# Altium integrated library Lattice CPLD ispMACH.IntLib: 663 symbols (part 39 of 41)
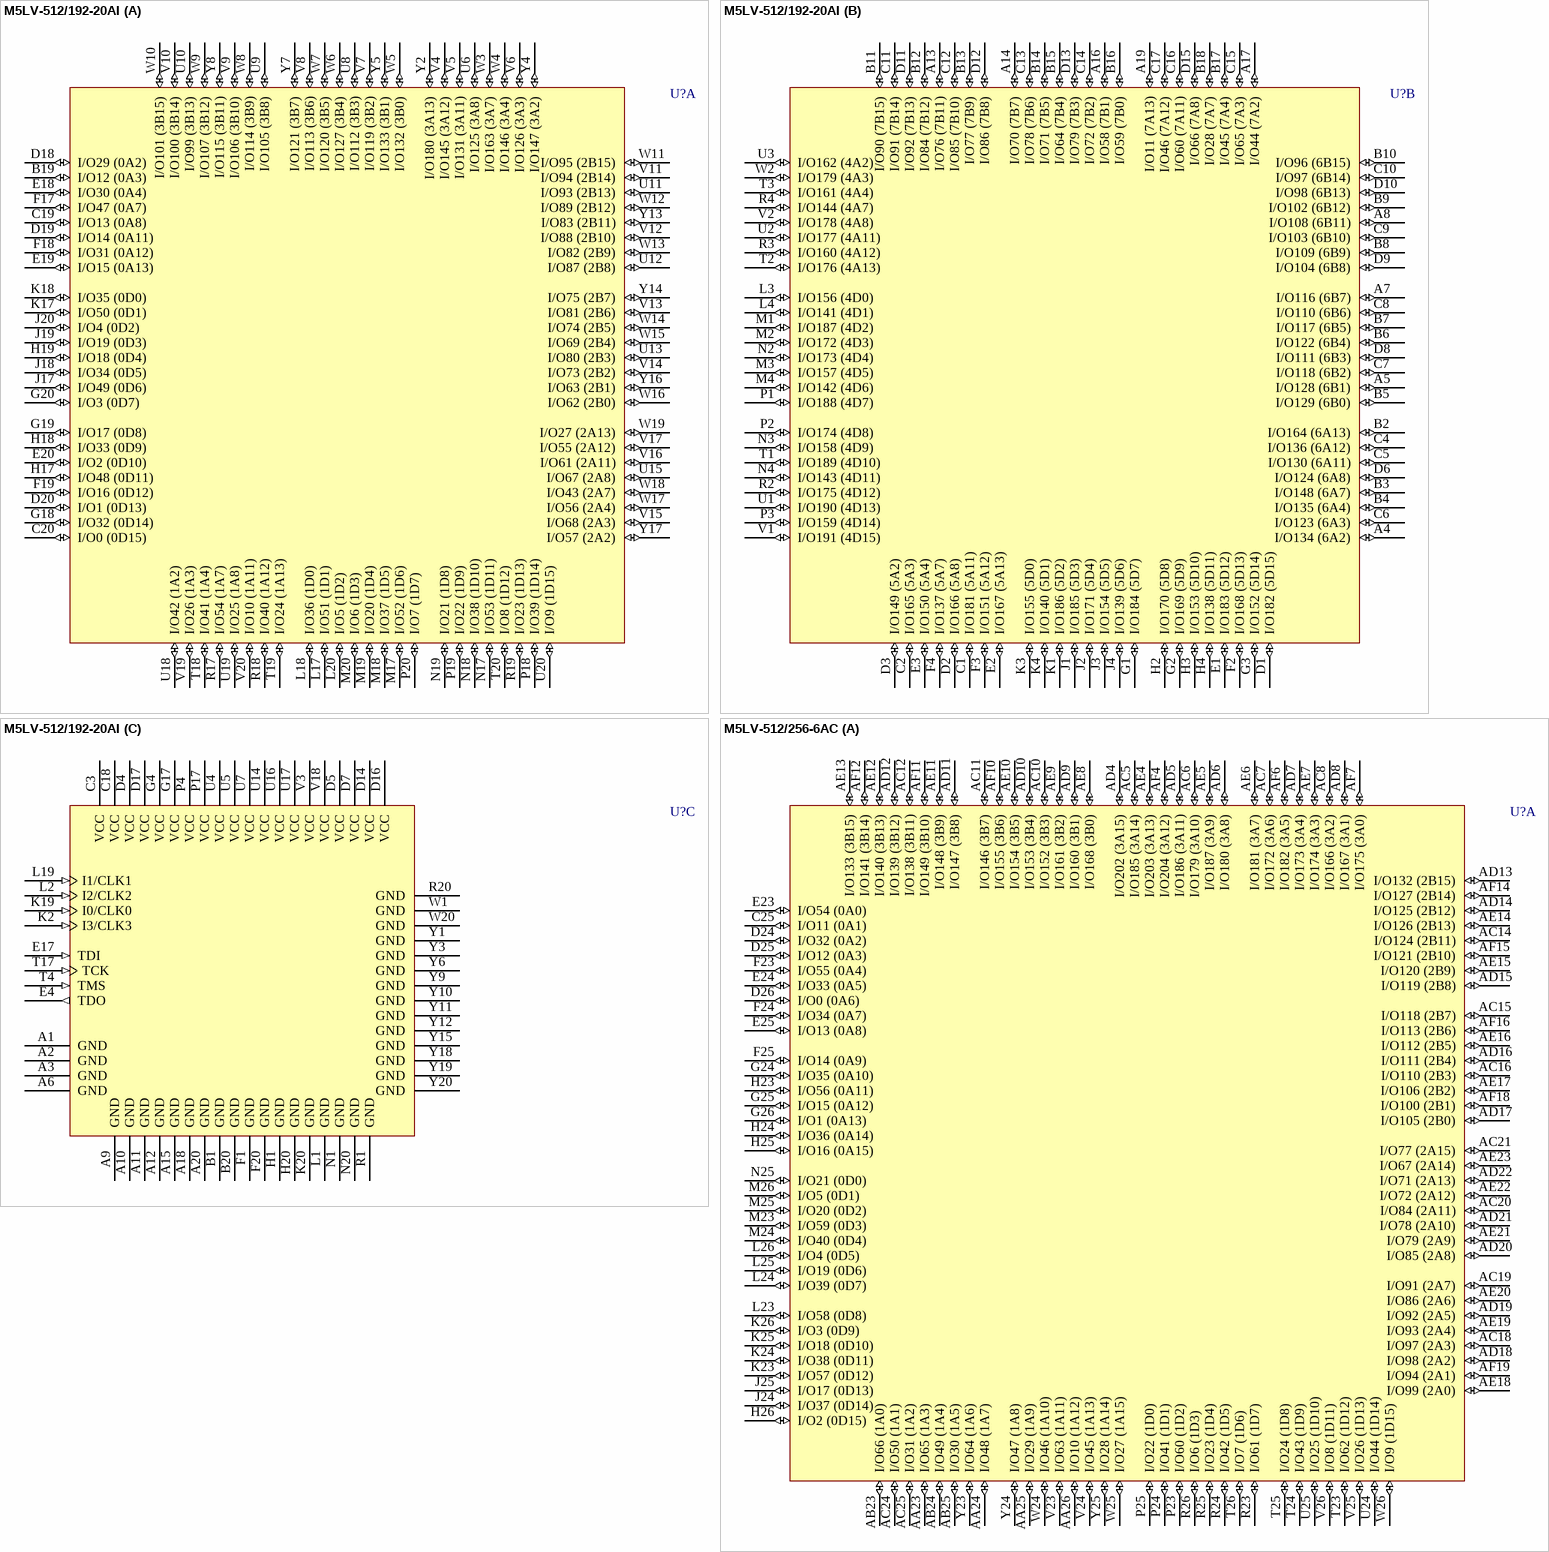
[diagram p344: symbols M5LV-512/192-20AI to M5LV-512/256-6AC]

## M5LV-512/192-20AI
designator U?
High-Density and High-I/O Complex PLD
footprint SBGA256 (BGA, 256-Leads, Body 27x27mm, Pitch 1.27mm)
3D model M5LV-SBGA256 (256-Ball Super Ball Grid Array (SBGA256))
part A pins: B19 I/O12 (0A3) (io), C19 I/O13 (0A8) (io), C20 I/O0 (0D15) (io), D18 I/O29 (0A2) (io), D19 I/O14 (0A11) (io), D20 I/O1 (0D13) (io), E18 I/O30 (0A4) (io), E19 I/O15 (0A13) (io), E20 I/O2 (0D10) (io), F17 I/O47 (0A7) (io), F18 I/O31 (0A12) (io), F19 I/O16 (0D12) (io), G18 I/O32 (0D14) (io), G19 I/O17 (0D8) (io), G20 I/O3 (0D7) (io), H17 I/O48 (0D11) (io), H18 I/O33 (0D9) (io), H19 I/O18 (0D4) (io), J17 I/O49 (0D6) (io), J18 I/O34 (0D5) (io), J19 I/O19 (0D3) (io), J20 I/O4 (0D2) (io), K17 I/O50 (0D1) (io), K18 I/O35 (0D0) (io), L17 I/O51 (1D1) (io), L18 I/O36 (1D0) (io), L20 I/O5 (1D2) (io), M17 I/O52 (1D6) (io), M18 I/O37 (1D5) (io), M19 I/O20 (1D4) (io), M20 I/O6 (1D3) (io), N17 I/O53 (1D11) (io), N18 I/O38 (1D10) (io), N19 I/O21 (1D8) (io), P18 I/O39 (1D14) (io), P19 I/O22 (1D9) (io), P20 I/O7 (1D7) (io), R17 I/O54 (1A7) (io), R18 I/O40 (1A12) (io), R19 I/O23 (1D13) (io), T18 I/O41 (1A4) (io), T19 I/O24 (1A13) (io), T20 I/O8 (1D12) (io), U6 I/O125 (3A8) (io), U8 I/O112 (3B3) (io), U9 I/O105 (3B8) (io), U10 I/O99 (3B13) (io), U11 I/O93 (2B13) (io), U12 I/O87 (2B8) (io), U13 I/O80 (2B3) (io), U15 I/O67 (2A8) (io), U18 I/O42 (1A2) (io), U19 I/O25 (1A8) (io), U20 I/O9 (1D15) (io), V4 I/O145 (3A12) (io), V5 I/O131 (3A11) (io), V6 I/O126 (3A3) (io), V7 I/O119 (3B2) (io), V8 I/O113 (3B6) (io), V9 I/O106 (3B10) (io), V10 I/O100 (3B14) (io), V11 I/O94 (2B14) (io), V12 I/O88 (2B10) (io), V13 I/O81 (2B6) (io), V14 I/O73 (2B2) (io), V15 I/O68 (2A3) (io), V16 I/O61 (2A11) (io), V17 I/O55 (2A12) (io), V19 I/O26 (1A3) (io), V20 I/O10 (1A11) (io), W3 I/O163 (3A7) (io), W4 I/O146 (3A4) (io), W5 I/O132 (3B0) (io), W6 I/O127 (3B4) (io), W7 I/O120 (3B5) (io), W8 I/O114 (3B9) (io), W9 I/O107 (3B12) (io), W10 I/O101 (3B15) (io), W11 I/O95 (2B15) (io), W12 I/O89 (2B12) (io), W13 I/O82 (2B9) (io), W14 I/O74 (2B5) (io), W15 I/O69 (2B4) (io), W16 I/O62 (2B0) (io), W17 I/O56 (2A4) (io), W18 I/O43 (2A7) (io), W19 I/O27 (2A13) (io), Y2 I/O180 (3A13) (io), Y4 I/O147 (3A2) (io), Y5 I/O133 (3B1) (io), Y7 I/O121 (3B7) (io), Y8 I/O115 (3B11) (io), Y13 I/O83 (2B11) (io), Y14 I/O75 (2B7) (io), Y16 I/O63 (2B1) (io), Y17 I/O57 (2A2) (io)
part B pins: A4 I/O134 (6A2) (io), A5 I/O128 (6B1) (io), A7 I/O116 (6B7) (io), A8 I/O108 (6B11) (io), A13 I/O76 (7B11) (io), A14 I/O70 (7B7) (io), A16 I/O58 (7B1) (io), A17 I/O44 (7A2) (io), A19 I/O11 (7A13) (io), B2 I/O164 (6A13) (io), B3 I/O148 (6A7) (io), B4 I/O135 (6A4) (io), B5 I/O129 (6B0) (io), B6 I/O122 (6B4) (io), B7 I/O117 (6B5) (io), B8 I/O109 (6B9) (io), B9 I/O102 (6B12) (io), B10 I/O96 (6B15) (io), B11 I/O90 (7B15) (io), B12 I/O84 (7B12) (io), B13 I/O77 (7B9) (io), B14 I/O71 (7B5) (io), B15 I/O64 (7B4) (io), B16 I/O59 (7B0) (io), B17 I/O45 (7A4) (io), B18 I/O28 (7A7) (io), C1 I/O181 (5A11) (io), C2 I/O165 (5A3) (io), C4 I/O136 (6A12) (io), C5 I/O130 (6A11) (io), C6 I/O123 (6A3) (io), C7 I/O118 (6B2) (io), C8 I/O110 (6B6) (io), C9 I/O103 (6B10) (io), C10 I/O97 (6B14) (io), C11 I/O91 (7B14) (io), C12 I/O85 (7B10) (io), C13 I/O78 (7B6) (io), C14 I/O72 (7B2) (io), C15 I/O65 (7A3) (io), C16 I/O60 (7A11) (io), C17 I/O46 (7A12) (io), D1 I/O182 (5D15) (io), D2 I/O166 (5A8) (io), D3 I/O149 (5A2) (io), D6 I/O124 (6A8) (io), D8 I/O111 (6B3) (io), D9 I/O104 (6B8) (io), D10 I/O98 (6B13) (io), D11 I/O92 (7B13) (io), D12 I/O86 (7B8) (io), D13 I/O79 (7B3) (io), D15 I/O66 (7A8) (io), E1 I/O183 (5D12) (io), E2 I/O167 (5A13) (io), E3 I/O150 (5A4) (io), F2 I/O168 (5D13) (io), F3 I/O151 (5A12) (io), F4 I/O137 (5A7) (io), G1 I/O184 (5D7) (io), G2 I/O169 (5D9) (io), G3 I/O152 (5D14) (io), H2 I/O170 (5D8) (io), H3 I/O153 (5D10) (io), H4 I/O138 (5D11) (io), J1 I/O185 (5D3) (io), J2 I/O171 (5D4) (io), J3 I/O154 (5D5) (io), J4 I/O139 (5D6) (io), K1 I/O186 (5D2) (io), K3 I/O155 (5D0) (io), K4 I/O140 (5D1) (io), L3 I/O156 (4D0) (io), L4 I/O141 (4D1) (io), M1 I/O187 (4D2) (io), M2 I/O172 (4D3) (io), M3 I/O157 (4D5) (io), M4 I/O142 (4D6) (io), N2 I/O173 (4D4) (io), N3 I/O158 (4D9) (io), N4 I/O143 (4D11) (io), P1 I/O188 (4D7) (io), P2 I/O174 (4D8) (io), P3 I/O159 (4D14) (io), R2 I/O175 (4D12) (io), R3 I/O160 (4A12) (io), R4 I/O144 (4A7) (io), T1 I/O189 (4D10) (io), T2 I/O176 (4A13) (io), T3 I/O161 (4A4) (io), U1 I/O190 (4D13) (io), U2 I/O177 (4A11) (io), U3 I/O162 (4A2) (io), V1 I/O191 (4D15) (io), V2 I/O178 (4A8) (io), W2 I/O179 (4A3) (io)
part C pins: A1 GND (power), A2 GND (power), A3 GND (power), A6 GND (power), A9 GND (power), A10 GND (power), A11 GND (power), A12 GND (power), A15 GND (power), A18 GND (power), A20 GND (power), B1 GND (power), B20 GND (power), C3 VCC (power), C18 VCC (power), D4 VCC (power), D5 VCC (power), D7 VCC (power), D14 VCC (power), D16 VCC (power), D17 VCC (power), E4 TDO (out), E17 TDI (in), F1 GND (power), F20 GND (power), G4 VCC (power), G17 VCC (power), H1 GND (power), H20 GND (power), K2 I3/CLK3 (in), K19 I0/CLK0 (in), K20 GND (power), L1 GND (power), L2 I2/CLK2 (in), L19 I1/CLK1 (in), N1 GND (power), N20 GND (power), P4 VCC (power), P17 VCC (power), R1 GND (power), R20 GND (power), T4 TMS (in), T17 TCK (in), U4 VCC (power), U5 VCC (power), U7 VCC (power), U14 VCC (power), U16 VCC (power), U17 VCC (power), V3 VCC (power), V18 VCC (power), W1 GND (power), W20 GND (power), Y1 GND (power), Y3 GND (power), Y6 GND (power), Y9 GND (power), Y10 GND (power), Y11 GND (power), Y12 GND (power), Y15 GND (power), Y18 GND (power), Y19 GND (power), Y20 GND (power)

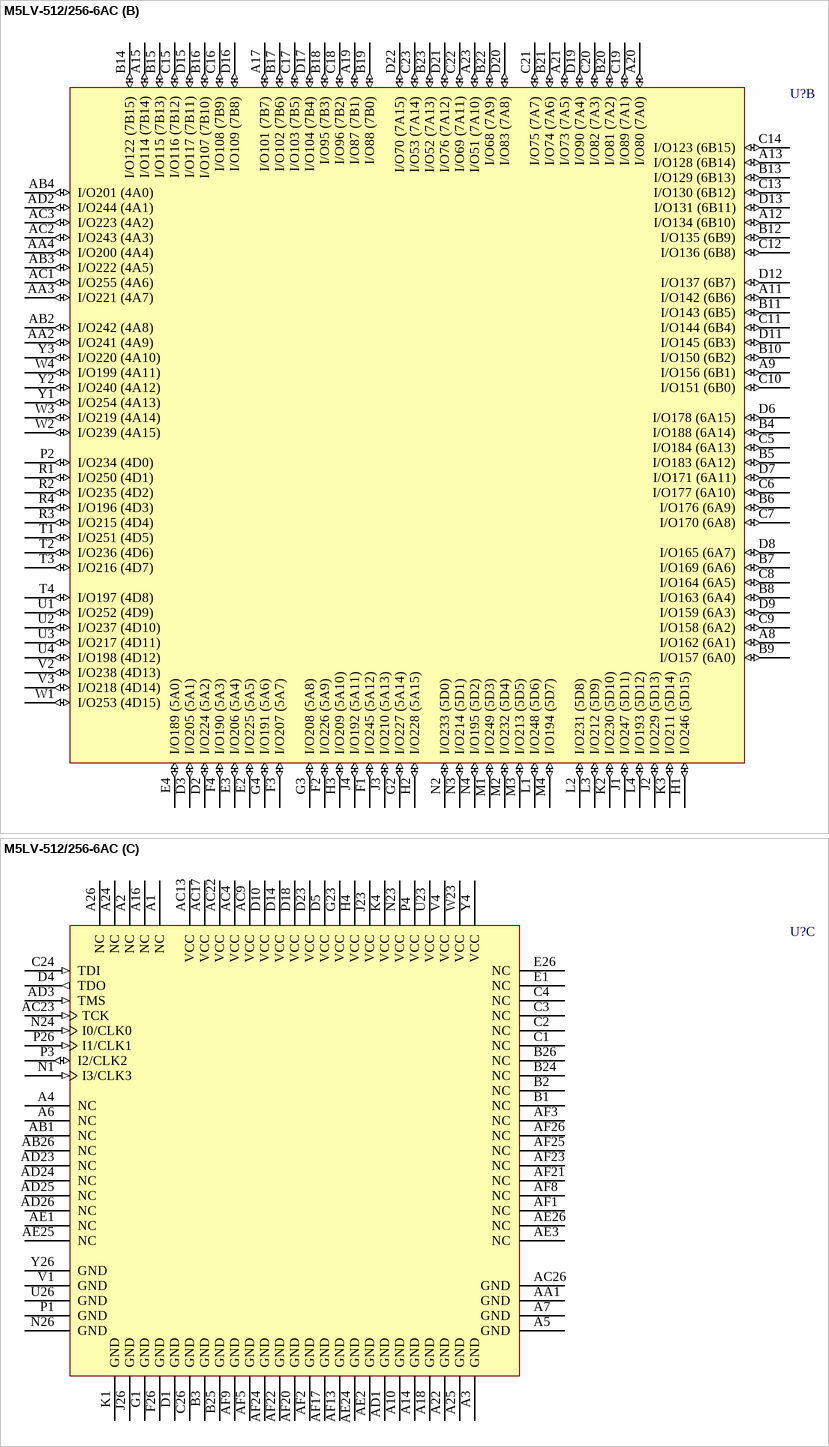
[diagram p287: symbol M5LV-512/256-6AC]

## M5LV-512/256-6AC
designator U?
High-Density and High-I/O Complex PLD
footprint SBGA352 (BGA, 352-Leads, Body 35x35mm, Pitch 1.27mm)
3D model M5LV-SBGA352 (352-Ball Super Ball Grid Array (SBGA352))
part A pins: AA23 I/O65 (1A3) (io), AA24 I/O48 (1A7) (io), AA25 I/O29 (1A9) (io), AA26 I/O10 (1A12) (io), AB23 I/O66 (1A0) (io), AB24 I/O49 (1A4) (io), AB25 I/O30 (1A5) (io), AC5 I/O185 (3A14) (io), AC6 I/O179 (3A10) (io), AC7 I/O172 (3A6) (io), AC8 I/O166 (3A2) (io), AC10 I/O152 (3B3) (io), AC11 I/O146 (3B7) (io), AC12 I/O138 (3B11) (io), AC14 I/O124 (2B11) (io), AC15 I/O118 (2B7) (io), AC16 I/O110 (2B3) (io), AC18 I/O97 (2A3) (io), AC19 I/O91 (2A7) (io), AC20 I/O84 (2A11) (io), AC21 I/O77 (2A15) (io), AC24 I/O50 (1A1) (io), AC25 I/O31 (1A2) (io), AD4 I/O202 (3A15) (io), AD5 I/O186 (3A11) (io), AD6 I/O180 (3A8) (io), AD7 I/O173 (3A4) (io), AD8 I/O167 (3A1) (io), AD9 I/O160 (3B1) (io), AD10 I/O153 (3B4) (io), AD11 I/O147 (3B8) (io), AD12 I/O139 (3B12) (io), AD13 I/O132 (2B15) (io), AD14 I/O125 (2B12) (io), AD15 I/O119 (2B8) (io), AD16 I/O111 (2B4) (io), AD17 I/O105 (2B0) (io), AD18 I/O98 (2A2) (io), AD19 I/O92 (2A5) (io), AD20 I/O85 (2A8) (io), AD21 I/O78 (2A10) (io), AD22 I/O71 (2A13) (io), AE4 I/O203 (3A13) (io), AE5 I/O187 (3A9) (io), AE6 I/O181 (3A7) (io), AE7 I/O174 (3A3) (io), AE8 I/O168 (3B0) (io), AE9 I/O161 (3B2) (io), AE10 I/O154 (3B5) (io), AE11 I/O148 (3B9) (io), AE12 I/O140 (3B13) (io), AE13 I/O133 (3B15) (io), AE14 I/O126 (2B13) (io), AE15 I/O120 (2B9) (io), AE16 I/O112 (2B5) (io), AE17 I/O106 (2B2) (io), AE18 I/O99 (2A0) (io), AE19 I/O93 (2A4) (io), AE20 I/O86 (2A6) (io), AE21 I/O79 (2A9) (io), AE22 I/O72 (2A12) (io), AE23 I/O67 (2A14) (io), AF4 I/O204 (3A12) (io), AF6 I/O182 (3A5) (io), AF7 I/O175 (3A0) (io), AF10 I/O155 (3B6) (io), AF11 I/O149 (3B10) (io), AF12 I/O141 (3B14) (io), AF14 I/O127 (2B14) (io), AF15 I/O121 (2B10) (io), AF16 I/O113 (2B6) (io), AF18 I/O100 (2B1) (io), AF19 I/O94 (2A1) (io), C25 I/O11 (0A1) (io), D24 I/O32 (0A2) (io), D25 I/O12 (0A3) (io), D26 I/O0 (0A6) (io), E23 I/O54 (0A0) (io), E24 I/O33 (0A5) (io), E25 I/O13 (0A8) (io), F23 I/O55 (0A4) (io), F24 I/O34 (0A7) (io), F25 I/O14 (0A9) (io), G24 I/O35 (0A10) (io), G25 I/O15 (0A12) (io), G26 I/O1 (0A13) (io), H23 I/O56 (0A11) (io), H24 I/O36 (0A14) (io), H25 I/O16 (0A15) (io), H26 I/O2 (0D15) (io), J24 I/O37 (0D14) (io), J25 I/O17 (0D13) (io), K23 I/O57 (0D12) (io), K24 I/O38 (0D11) (io), K25 I/O18 (0D10) (io), K26 I/O3 (0D9) (io), L23 I/O58 (0D8) (io), L24 I/O39 (0D7) (io), L25 I/O19 (0D6) (io), L26 I/O4 (0D5) (io), M23 I/O59 (0D3) (io), M24 I/O40 (0D4) (io), M25 I/O20 (0D2) (io), M26 I/O5 (0D1) (io), N25 I/O21 (0D0) (io), P23 I/O60 (1D2) (io), P24 I/O41 (1D1) (io), P25 I/O22 (1D0) (io), R23 I/O61 (1D7) (io), R24 I/O42 (1D5) (io), R25 I/O23 (1D4) (io), R26 I/O6 (1D3) (io), T23 I/O62 (1D12) (io), T24 I/O43 (1D9) (io), T25 I/O24 (1D8) (io), T26 I/O7 (1D6) (io), U24 I/O44 (1D14) (io), U25 I/O25 (1D10) (io), V23 I/O63 (1A11) (io), V24 I/O45 (1A13) (io), V25 I/O26 (1D13) (io), V26 I/O8 (1D11) (io), W24 I/O46 (1A10) (io), W25 I/O27 (1A15) (io), W26 I/O9 (1D15) (io), Y23 I/O64 (1A6) (io), Y24 I/O47 (1A8) (io), Y25 I/O28 (1A14) (io)
part B pins: A8 I/O162 (6A1) (io), A9 I/O156 (6B1) (io), A11 I/O142 (6B6) (io), A12 I/O134 (6B10) (io), A13 I/O128 (6B14) (io), A15 I/O114 (7B14) (io), A17 I/O101 (7B7) (io), A19 I/O87 (7B1) (io), A20 I/O80 (7A0) (io), A21 I/O73 (7A5) (io), A23 I/O51 (7A10) (io), AA2 I/O241 (4A9) (io), AA3 I/O221 (4A7) (io), AA4 I/O200 (4A4) (io), AB2 I/O242 (4A8) (io), AB3 I/O222 (4A5) (io), AB4 I/O201 (4A0) (io), AC1 I/O255 (4A6) (io), AC2 I/O243 (4A3) (io), AC3 I/O223 (4A2) (io), AD2 I/O244 (4A1) (io), B4 I/O188 (6A14) (io), B5 I/O183 (6A12) (io), B6 I/O176 (6A9) (io), B7 I/O169 (6A6) (io), B8 I/O163 (6A4) (io), B9 I/O157 (6A0) (io), B10 I/O150 (6B2) (io), B11 I/O143 (6B5) (io), B12 I/O135 (6B9) (io), B13 I/O129 (6B13) (io), B14 I/O122 (7B15) (io), B15 I/O115 (7B13) (io), B16 I/O107 (7B10) (io), B17 I/O102 (7B6) (io), B18 I/O95 (7B3) (io), B19 I/O88 (7B0) (io), B20 I/O81 (7A2) (io), B21 I/O74 (7A6) (io), B22 I/O68 (7A9) (io), B23 I/O52 (7A13) (io), C5 I/O184 (6A13) (io), C6 I/O177 (6A10) (io), C7 I/O170 (6A8) (io), C8 I/O164 (6A5) (io), C9 I/O158 (6A2) (io), C10 I/O151 (6B0) (io), C11 I/O144 (6B4) (io), C12 I/O136 (6B8) (io), C13 I/O130 (6B12) (io), C14 I/O123 (6B15) (io), C15 I/O116 (7B12) (io), C16 I/O108 (7B9) (io), C17 I/O103 (7B5) (io), C18 I/O96 (7B2) (io), C19 I/O89 (7A1) (io), C20 I/O82 (7A3) (io), C21 I/O75 (7A7) (io), C22 I/O69 (7A11) (io), C23 I/O53 (7A14) (io), D2 I/O224 (5A2) (io), D3 I/O205 (5A1) (io), D6 I/O178 (6A15) (io), D7 I/O171 (6A11) (io), D8 I/O165 (6A7) (io), D9 I/O159 (6A3) (io), D11 I/O145 (6B3) (io), D12 I/O137 (6B7) (io), D13 I/O131 (6B11) (io), D15 I/O117 (7B11) (io), D16 I/O109 (7B8) (io), D17 I/O104 (7B4) (io), D19 I/O90 (7A4) (io), D20 I/O83 (7A8) (io), D21 I/O76 (7A12) (io), D22 I/O70 (7A15) (io), E2 I/O225 (5A5) (io), E3 I/O206 (5A4) (io), E4 I/O189 (5A0) (io), F1 I/O245 (5A12) (io), F2 I/O226 (5A9) (io), F3 I/O207 (5A7) (io), F4 I/O190 (5A3) (io), G2 I/O227 (5A14) (io), G3 I/O208 (5A8) (io), G4 I/O191 (5A6) (io), H1 I/O246 (5D15) (io), H2 I/O228 (5A15) (io), H3 I/O209 (5A10) (io), J1 I/O247 (5D11) (io), J2 I/O229 (5D13) (io), J3 I/O210 (5A13) (io), J4 I/O192 (5A11) (io), K2 I/O230 (5D10) (io), K3 I/O211 (5D14) (io), L1 I/O248 (5D6) (io), L2 I/O231 (5D8) (io), L3 I/O212 (5D9) (io), L4 I/O193 (5D12) (io), M1 I/O249 (5D3) (io), M2 I/O232 (5D4) (io), M3 I/O213 (5D5) (io), M4 I/O194 (5D7) (io), N2 I/O233 (5D0) (io), N3 I/O214 (5D1) (io), N4 I/O195 (5D2) (io), P2 I/O234 (4D0) (io), R1 I/O250 (4D1) (io), R2 I/O235 (4D2) (io), R3 I/O215 (4D4) (io), R4 I/O196 (4D3) (io), T1 I/O251 (4D5) (io), T2 I/O236 (4D6) (io), T3 I/O216 (4D7) (io), T4 I/O197 (4D8) (io), U1 I/O252 (4D9) (io), U2 I/O237 (4D10) (io), U3 I/O217 (4D11) (io), U4 I/O198 (4D12) (io), V2 I/O238 (4D13) (io), V3 I/O218 (4D14) (io), W1 I/O253 (4D15) (io), W2 I/O239 (4A15) (io), W3 I/O219 (4A14) (io), W4 I/O199 (4A11) (io), Y1 I/O254 (4A13) (io), Y2 I/O240 (4A12) (io), Y3 I/O220 (4A10) (io)
part C pins: A1 NC, A2 NC, A3 GND (power), A4 NC, A5 GND (power), A6 NC, A7 GND (power), A10 GND (power), A14 GND (power), A16 NC, A18 GND (power), A22 GND (power), A24 NC, A25 GND (power), A26 NC, AA1 GND (power), AB1 NC, AB26 NC, AC4 VCC (power), AC9 VCC (power), AC13 VCC (power), AC17 VCC (power), AC22 VCC (power), AC23 TCK (in), AC26 GND (power), AD1 GND (power), AD3 TMS (in), AD23 NC, AD24 NC, AD25 NC, AD26 NC, AE1 NC, AE2 GND (power), AE3 NC, AE24 GND (power), AE25 NC, AE26 NC, AF1 NC, AF2 GND (power), AF3 NC, AF5 GND (power), AF8 NC, AF9 GND (power), AF13 GND (power), AF17 GND (power), AF20 GND (power), AF21 NC, AF22 GND (power), AF23 NC, AF24 GND (power), AF25 NC, AF26 NC, B1 NC, B2 NC, B3 GND (power), B24 NC, B25 GND (power), B26 NC, C1 NC, C2 NC, C3 NC, C4 NC, C24 TDI (in), C26 GND (power), D1 GND (power), D4 TDO (out), D5 VCC (power), D10 VCC (power), D14 VCC (power), D18 VCC (power), D23 VCC (power), E1 NC, E26 NC, F26 GND (power), G1 GND (power), G23 VCC (power), H4 VCC (power), J23 VCC (power), J26 GND (power), K1 GND (power), K4 VCC (power), N1 I3/CLK3 (in), N23 VCC (power), N24 I0/CLK0 (in), N26 GND (power), P1 GND (power), P3 I2/CLK2 (io), P4 VCC (power), P26 I1/CLK1 (in), U23 VCC (power), U26 GND (power), V1 GND (power), V4 VCC (power), W23 VCC (power), Y4 VCC (power), Y26 GND (power)

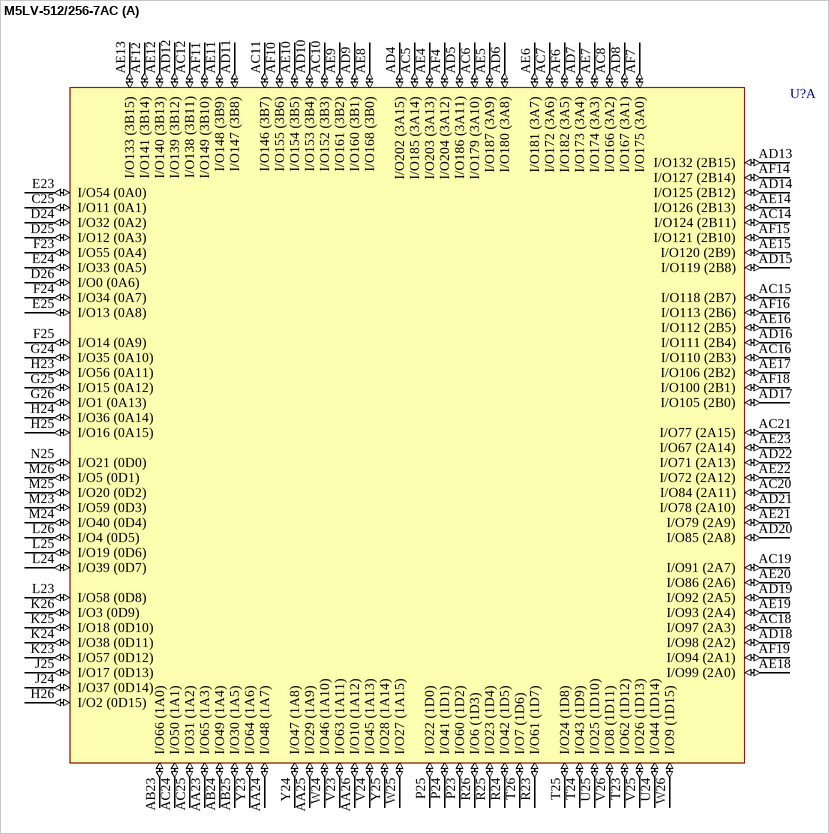
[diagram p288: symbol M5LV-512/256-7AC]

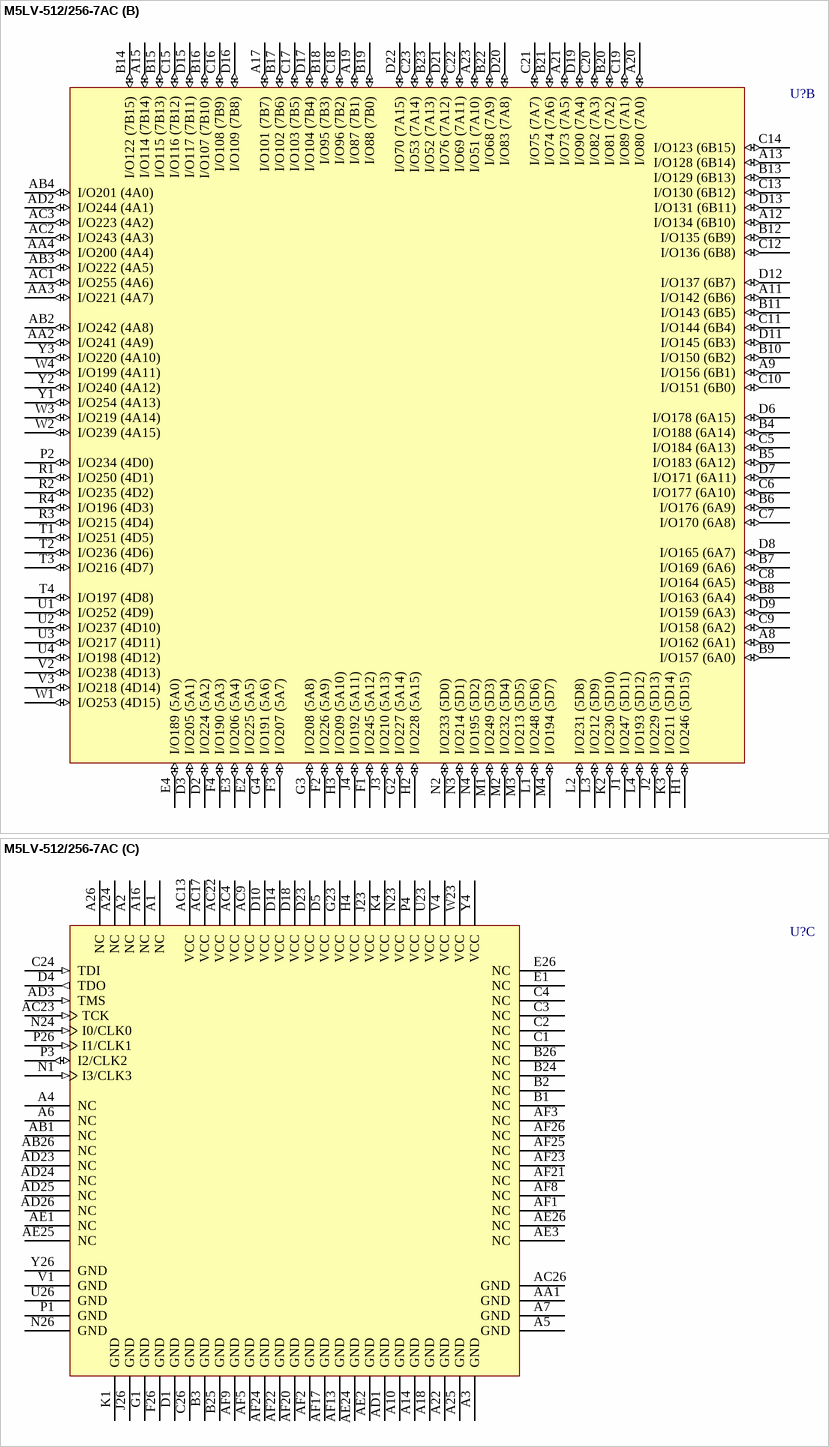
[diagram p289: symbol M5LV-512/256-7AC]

## M5LV-512/256-7AC
designator U?
High-Density and High-I/O Complex PLD
footprint SBGA352 (BGA, 352-Leads, Body 35x35mm, Pitch 1.27mm)
3D model M5LV-SBGA352 (352-Ball Super Ball Grid Array (SBGA352))
part A pins: AA23 I/O65 (1A3) (io), AA24 I/O48 (1A7) (io), AA25 I/O29 (1A9) (io), AA26 I/O10 (1A12) (io), AB23 I/O66 (1A0) (io), AB24 I/O49 (1A4) (io), AB25 I/O30 (1A5) (io), AC5 I/O185 (3A14) (io), AC6 I/O179 (3A10) (io), AC7 I/O172 (3A6) (io), AC8 I/O166 (3A2) (io), AC10 I/O152 (3B3) (io), AC11 I/O146 (3B7) (io), AC12 I/O138 (3B11) (io), AC14 I/O124 (2B11) (io), AC15 I/O118 (2B7) (io), AC16 I/O110 (2B3) (io), AC18 I/O97 (2A3) (io), AC19 I/O91 (2A7) (io), AC20 I/O84 (2A11) (io), AC21 I/O77 (2A15) (io), AC24 I/O50 (1A1) (io), AC25 I/O31 (1A2) (io), AD4 I/O202 (3A15) (io), AD5 I/O186 (3A11) (io), AD6 I/O180 (3A8) (io), AD7 I/O173 (3A4) (io), AD8 I/O167 (3A1) (io), AD9 I/O160 (3B1) (io), AD10 I/O153 (3B4) (io), AD11 I/O147 (3B8) (io), AD12 I/O139 (3B12) (io), AD13 I/O132 (2B15) (io), AD14 I/O125 (2B12) (io), AD15 I/O119 (2B8) (io), AD16 I/O111 (2B4) (io), AD17 I/O105 (2B0) (io), AD18 I/O98 (2A2) (io), AD19 I/O92 (2A5) (io), AD20 I/O85 (2A8) (io), AD21 I/O78 (2A10) (io), AD22 I/O71 (2A13) (io), AE4 I/O203 (3A13) (io), AE5 I/O187 (3A9) (io), AE6 I/O181 (3A7) (io), AE7 I/O174 (3A3) (io), AE8 I/O168 (3B0) (io), AE9 I/O161 (3B2) (io), AE10 I/O154 (3B5) (io), AE11 I/O148 (3B9) (io), AE12 I/O140 (3B13) (io), AE13 I/O133 (3B15) (io), AE14 I/O126 (2B13) (io), AE15 I/O120 (2B9) (io), AE16 I/O112 (2B5) (io), AE17 I/O106 (2B2) (io), AE18 I/O99 (2A0) (io), AE19 I/O93 (2A4) (io), AE20 I/O86 (2A6) (io), AE21 I/O79 (2A9) (io), AE22 I/O72 (2A12) (io), AE23 I/O67 (2A14) (io), AF4 I/O204 (3A12) (io), AF6 I/O182 (3A5) (io), AF7 I/O175 (3A0) (io), AF10 I/O155 (3B6) (io), AF11 I/O149 (3B10) (io), AF12 I/O141 (3B14) (io), AF14 I/O127 (2B14) (io), AF15 I/O121 (2B10) (io), AF16 I/O113 (2B6) (io), AF18 I/O100 (2B1) (io), AF19 I/O94 (2A1) (io), C25 I/O11 (0A1) (io), D24 I/O32 (0A2) (io), D25 I/O12 (0A3) (io), D26 I/O0 (0A6) (io), E23 I/O54 (0A0) (io), E24 I/O33 (0A5) (io), E25 I/O13 (0A8) (io), F23 I/O55 (0A4) (io), F24 I/O34 (0A7) (io), F25 I/O14 (0A9) (io), G24 I/O35 (0A10) (io), G25 I/O15 (0A12) (io), G26 I/O1 (0A13) (io), H23 I/O56 (0A11) (io), H24 I/O36 (0A14) (io), H25 I/O16 (0A15) (io), H26 I/O2 (0D15) (io), J24 I/O37 (0D14) (io), J25 I/O17 (0D13) (io), K23 I/O57 (0D12) (io), K24 I/O38 (0D11) (io), K25 I/O18 (0D10) (io), K26 I/O3 (0D9) (io), L23 I/O58 (0D8) (io), L24 I/O39 (0D7) (io), L25 I/O19 (0D6) (io), L26 I/O4 (0D5) (io), M23 I/O59 (0D3) (io), M24 I/O40 (0D4) (io), M25 I/O20 (0D2) (io), M26 I/O5 (0D1) (io), N25 I/O21 (0D0) (io), P23 I/O60 (1D2) (io), P24 I/O41 (1D1) (io), P25 I/O22 (1D0) (io), R23 I/O61 (1D7) (io), R24 I/O42 (1D5) (io), R25 I/O23 (1D4) (io), R26 I/O6 (1D3) (io), T23 I/O62 (1D12) (io), T24 I/O43 (1D9) (io), T25 I/O24 (1D8) (io), T26 I/O7 (1D6) (io), U24 I/O44 (1D14) (io), U25 I/O25 (1D10) (io), V23 I/O63 (1A11) (io), V24 I/O45 (1A13) (io), V25 I/O26 (1D13) (io), V26 I/O8 (1D11) (io), W24 I/O46 (1A10) (io), W25 I/O27 (1A15) (io), W26 I/O9 (1D15) (io), Y23 I/O64 (1A6) (io), Y24 I/O47 (1A8) (io), Y25 I/O28 (1A14) (io)
part B pins: A8 I/O162 (6A1) (io), A9 I/O156 (6B1) (io), A11 I/O142 (6B6) (io), A12 I/O134 (6B10) (io), A13 I/O128 (6B14) (io), A15 I/O114 (7B14) (io), A17 I/O101 (7B7) (io), A19 I/O87 (7B1) (io), A20 I/O80 (7A0) (io), A21 I/O73 (7A5) (io), A23 I/O51 (7A10) (io), AA2 I/O241 (4A9) (io), AA3 I/O221 (4A7) (io), AA4 I/O200 (4A4) (io), AB2 I/O242 (4A8) (io), AB3 I/O222 (4A5) (io), AB4 I/O201 (4A0) (io), AC1 I/O255 (4A6) (io), AC2 I/O243 (4A3) (io), AC3 I/O223 (4A2) (io), AD2 I/O244 (4A1) (io), B4 I/O188 (6A14) (io), B5 I/O183 (6A12) (io), B6 I/O176 (6A9) (io), B7 I/O169 (6A6) (io), B8 I/O163 (6A4) (io), B9 I/O157 (6A0) (io), B10 I/O150 (6B2) (io), B11 I/O143 (6B5) (io), B12 I/O135 (6B9) (io), B13 I/O129 (6B13) (io), B14 I/O122 (7B15) (io), B15 I/O115 (7B13) (io), B16 I/O107 (7B10) (io), B17 I/O102 (7B6) (io), B18 I/O95 (7B3) (io), B19 I/O88 (7B0) (io), B20 I/O81 (7A2) (io), B21 I/O74 (7A6) (io), B22 I/O68 (7A9) (io), B23 I/O52 (7A13) (io), C5 I/O184 (6A13) (io), C6 I/O177 (6A10) (io), C7 I/O170 (6A8) (io), C8 I/O164 (6A5) (io), C9 I/O158 (6A2) (io), C10 I/O151 (6B0) (io), C11 I/O144 (6B4) (io), C12 I/O136 (6B8) (io), C13 I/O130 (6B12) (io), C14 I/O123 (6B15) (io), C15 I/O116 (7B12) (io), C16 I/O108 (7B9) (io), C17 I/O103 (7B5) (io), C18 I/O96 (7B2) (io), C19 I/O89 (7A1) (io), C20 I/O82 (7A3) (io), C21 I/O75 (7A7) (io), C22 I/O69 (7A11) (io), C23 I/O53 (7A14) (io), D2 I/O224 (5A2) (io), D3 I/O205 (5A1) (io), D6 I/O178 (6A15) (io), D7 I/O171 (6A11) (io), D8 I/O165 (6A7) (io), D9 I/O159 (6A3) (io), D11 I/O145 (6B3) (io), D12 I/O137 (6B7) (io), D13 I/O131 (6B11) (io), D15 I/O117 (7B11) (io), D16 I/O109 (7B8) (io), D17 I/O104 (7B4) (io), D19 I/O90 (7A4) (io), D20 I/O83 (7A8) (io), D21 I/O76 (7A12) (io), D22 I/O70 (7A15) (io), E2 I/O225 (5A5) (io), E3 I/O206 (5A4) (io), E4 I/O189 (5A0) (io), F1 I/O245 (5A12) (io), F2 I/O226 (5A9) (io), F3 I/O207 (5A7) (io), F4 I/O190 (5A3) (io), G2 I/O227 (5A14) (io), G3 I/O208 (5A8) (io), G4 I/O191 (5A6) (io), H1 I/O246 (5D15) (io), H2 I/O228 (5A15) (io), H3 I/O209 (5A10) (io), J1 I/O247 (5D11) (io), J2 I/O229 (5D13) (io), J3 I/O210 (5A13) (io), J4 I/O192 (5A11) (io), K2 I/O230 (5D10) (io), K3 I/O211 (5D14) (io), L1 I/O248 (5D6) (io), L2 I/O231 (5D8) (io), L3 I/O212 (5D9) (io), L4 I/O193 (5D12) (io), M1 I/O249 (5D3) (io), M2 I/O232 (5D4) (io), M3 I/O213 (5D5) (io), M4 I/O194 (5D7) (io), N2 I/O233 (5D0) (io), N3 I/O214 (5D1) (io), N4 I/O195 (5D2) (io), P2 I/O234 (4D0) (io), R1 I/O250 (4D1) (io), R2 I/O235 (4D2) (io), R3 I/O215 (4D4) (io), R4 I/O196 (4D3) (io), T1 I/O251 (4D5) (io), T2 I/O236 (4D6) (io), T3 I/O216 (4D7) (io), T4 I/O197 (4D8) (io), U1 I/O252 (4D9) (io), U2 I/O237 (4D10) (io), U3 I/O217 (4D11) (io), U4 I/O198 (4D12) (io), V2 I/O238 (4D13) (io), V3 I/O218 (4D14) (io), W1 I/O253 (4D15) (io), W2 I/O239 (4A15) (io), W3 I/O219 (4A14) (io), W4 I/O199 (4A11) (io), Y1 I/O254 (4A13) (io), Y2 I/O240 (4A12) (io), Y3 I/O220 (4A10) (io)
part C pins: A1 NC, A2 NC, A3 GND (power), A4 NC, A5 GND (power), A6 NC, A7 GND (power), A10 GND (power), A14 GND (power), A16 NC, A18 GND (power), A22 GND (power), A24 NC, A25 GND (power), A26 NC, AA1 GND (power), AB1 NC, AB26 NC, AC4 VCC (power), AC9 VCC (power), AC13 VCC (power), AC17 VCC (power), AC22 VCC (power), AC23 TCK (in), AC26 GND (power), AD1 GND (power), AD3 TMS (in), AD23 NC, AD24 NC, AD25 NC, AD26 NC, AE1 NC, AE2 GND (power), AE3 NC, AE24 GND (power), AE25 NC, AE26 NC, AF1 NC, AF2 GND (power), AF3 NC, AF5 GND (power), AF8 NC, AF9 GND (power), AF13 GND (power), AF17 GND (power), AF20 GND (power), AF21 NC, AF22 GND (power), AF23 NC, AF24 GND (power), AF25 NC, AF26 NC, B1 NC, B2 NC, B3 GND (power), B24 NC, B25 GND (power), B26 NC, C1 NC, C2 NC, C3 NC, C4 NC, C24 TDI (in), C26 GND (power), D1 GND (power), D4 TDO (out), D5 VCC (power), D10 VCC (power), D14 VCC (power), D18 VCC (power), D23 VCC (power), E1 NC, E26 NC, F26 GND (power), G1 GND (power), G23 VCC (power), H4 VCC (power), J23 VCC (power), J26 GND (power), K1 GND (power), K4 VCC (power), N1 I3/CLK3 (in), N23 VCC (power), N24 I0/CLK0 (in), N26 GND (power), P1 GND (power), P3 I2/CLK2 (io), P4 VCC (power), P26 I1/CLK1 (in), U23 VCC (power), U26 GND (power), V1 GND (power), V4 VCC (power), W23 VCC (power), Y4 VCC (power), Y26 GND (power)

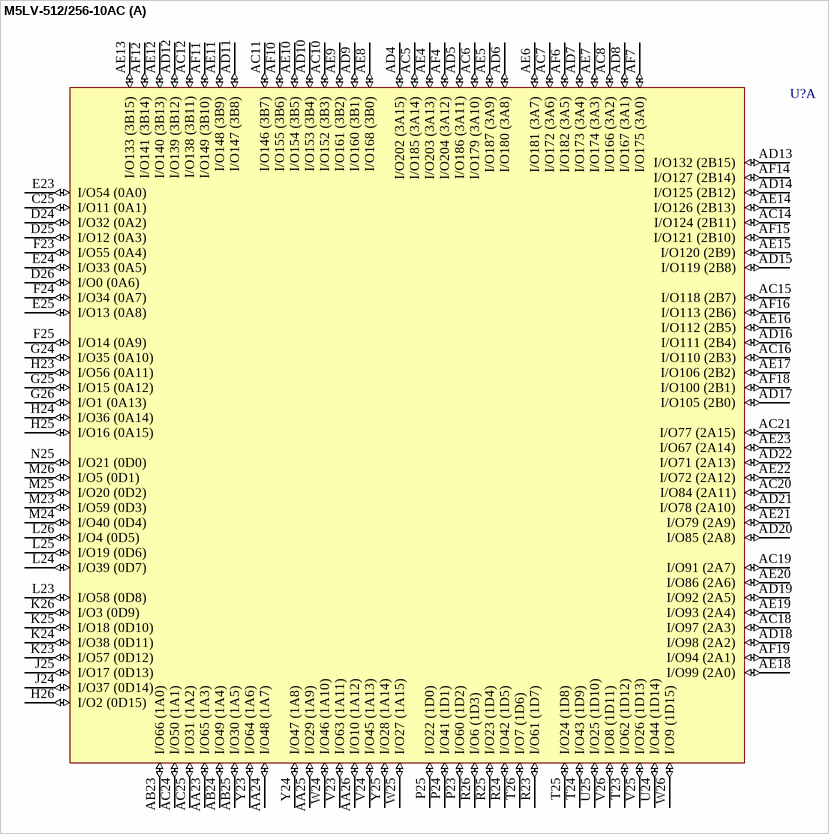
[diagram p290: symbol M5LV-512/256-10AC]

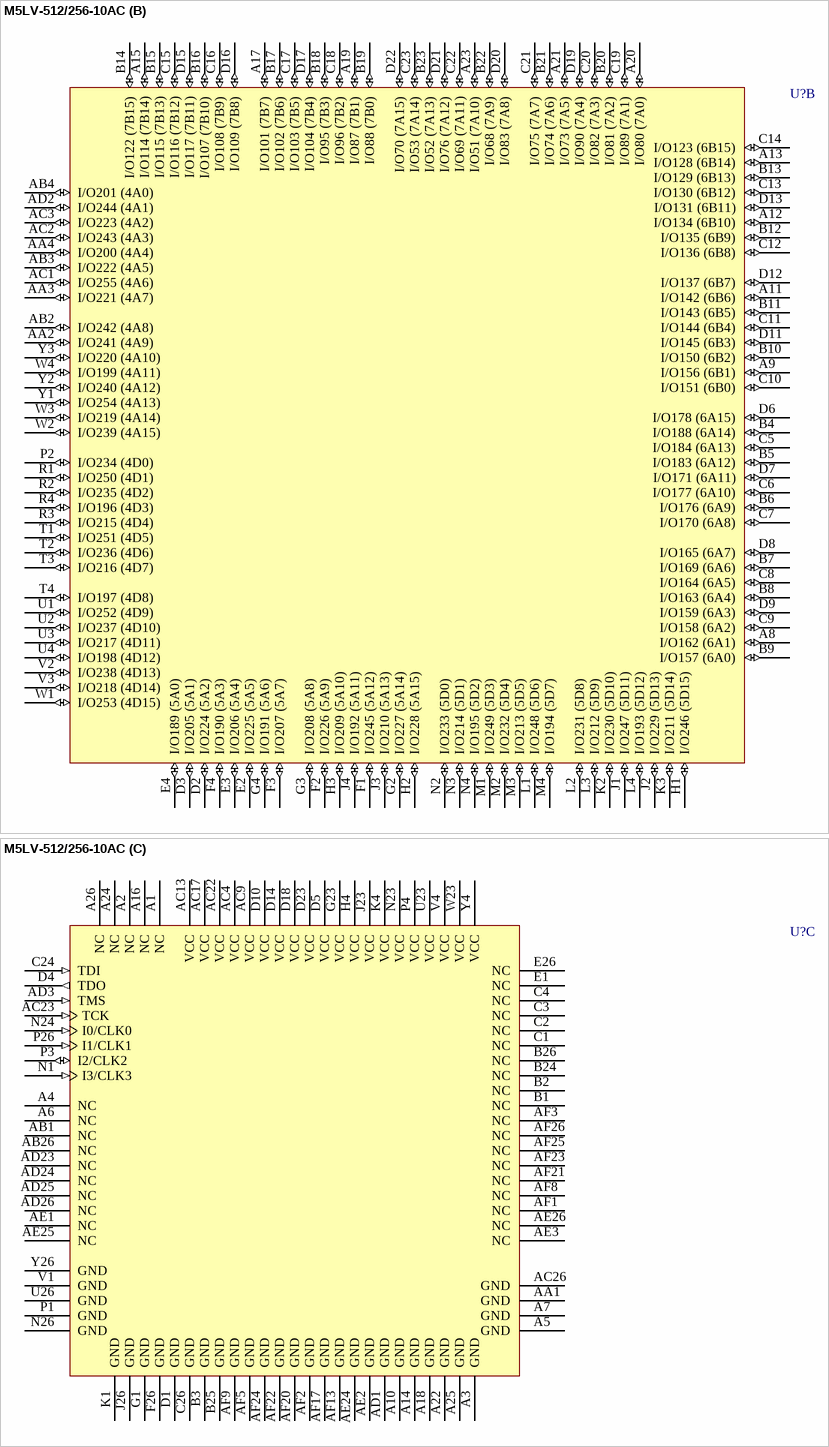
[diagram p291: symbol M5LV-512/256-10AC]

## M5LV-512/256-10AC
designator U?
High-Density and High-I/O Complex PLD
footprint SBGA352 (BGA, 352-Leads, Body 35x35mm, Pitch 1.27mm)
3D model M5LV-SBGA352 (352-Ball Super Ball Grid Array (SBGA352))
part A pins: AA23 I/O65 (1A3) (io), AA24 I/O48 (1A7) (io), AA25 I/O29 (1A9) (io), AA26 I/O10 (1A12) (io), AB23 I/O66 (1A0) (io), AB24 I/O49 (1A4) (io), AB25 I/O30 (1A5) (io), AC5 I/O185 (3A14) (io), AC6 I/O179 (3A10) (io), AC7 I/O172 (3A6) (io), AC8 I/O166 (3A2) (io), AC10 I/O152 (3B3) (io), AC11 I/O146 (3B7) (io), AC12 I/O138 (3B11) (io), AC14 I/O124 (2B11) (io), AC15 I/O118 (2B7) (io), AC16 I/O110 (2B3) (io), AC18 I/O97 (2A3) (io), AC19 I/O91 (2A7) (io), AC20 I/O84 (2A11) (io), AC21 I/O77 (2A15) (io), AC24 I/O50 (1A1) (io), AC25 I/O31 (1A2) (io), AD4 I/O202 (3A15) (io), AD5 I/O186 (3A11) (io), AD6 I/O180 (3A8) (io), AD7 I/O173 (3A4) (io), AD8 I/O167 (3A1) (io), AD9 I/O160 (3B1) (io), AD10 I/O153 (3B4) (io), AD11 I/O147 (3B8) (io), AD12 I/O139 (3B12) (io), AD13 I/O132 (2B15) (io), AD14 I/O125 (2B12) (io), AD15 I/O119 (2B8) (io), AD16 I/O111 (2B4) (io), AD17 I/O105 (2B0) (io), AD18 I/O98 (2A2) (io), AD19 I/O92 (2A5) (io), AD20 I/O85 (2A8) (io), AD21 I/O78 (2A10) (io), AD22 I/O71 (2A13) (io), AE4 I/O203 (3A13) (io), AE5 I/O187 (3A9) (io), AE6 I/O181 (3A7) (io), AE7 I/O174 (3A3) (io), AE8 I/O168 (3B0) (io), AE9 I/O161 (3B2) (io), AE10 I/O154 (3B5) (io), AE11 I/O148 (3B9) (io), AE12 I/O140 (3B13) (io), AE13 I/O133 (3B15) (io), AE14 I/O126 (2B13) (io), AE15 I/O120 (2B9) (io), AE16 I/O112 (2B5) (io), AE17 I/O106 (2B2) (io), AE18 I/O99 (2A0) (io), AE19 I/O93 (2A4) (io), AE20 I/O86 (2A6) (io), AE21 I/O79 (2A9) (io), AE22 I/O72 (2A12) (io), AE23 I/O67 (2A14) (io), AF4 I/O204 (3A12) (io), AF6 I/O182 (3A5) (io), AF7 I/O175 (3A0) (io), AF10 I/O155 (3B6) (io), AF11 I/O149 (3B10) (io), AF12 I/O141 (3B14) (io), AF14 I/O127 (2B14) (io), AF15 I/O121 (2B10) (io), AF16 I/O113 (2B6) (io), AF18 I/O100 (2B1) (io), AF19 I/O94 (2A1) (io), C25 I/O11 (0A1) (io), D24 I/O32 (0A2) (io), D25 I/O12 (0A3) (io), D26 I/O0 (0A6) (io), E23 I/O54 (0A0) (io), E24 I/O33 (0A5) (io), E25 I/O13 (0A8) (io), F23 I/O55 (0A4) (io), F24 I/O34 (0A7) (io), F25 I/O14 (0A9) (io), G24 I/O35 (0A10) (io), G25 I/O15 (0A12) (io), G26 I/O1 (0A13) (io), H23 I/O56 (0A11) (io), H24 I/O36 (0A14) (io), H25 I/O16 (0A15) (io), H26 I/O2 (0D15) (io), J24 I/O37 (0D14) (io), J25 I/O17 (0D13) (io), K23 I/O57 (0D12) (io), K24 I/O38 (0D11) (io), K25 I/O18 (0D10) (io), K26 I/O3 (0D9) (io), L23 I/O58 (0D8) (io), L24 I/O39 (0D7) (io), L25 I/O19 (0D6) (io), L26 I/O4 (0D5) (io), M23 I/O59 (0D3) (io), M24 I/O40 (0D4) (io), M25 I/O20 (0D2) (io), M26 I/O5 (0D1) (io), N25 I/O21 (0D0) (io), P23 I/O60 (1D2) (io), P24 I/O41 (1D1) (io), P25 I/O22 (1D0) (io), R23 I/O61 (1D7) (io), R24 I/O42 (1D5) (io), R25 I/O23 (1D4) (io), R26 I/O6 (1D3) (io), T23 I/O62 (1D12) (io), T24 I/O43 (1D9) (io), T25 I/O24 (1D8) (io), T26 I/O7 (1D6) (io), U24 I/O44 (1D14) (io), U25 I/O25 (1D10) (io), V23 I/O63 (1A11) (io), V24 I/O45 (1A13) (io), V25 I/O26 (1D13) (io), V26 I/O8 (1D11) (io), W24 I/O46 (1A10) (io), W25 I/O27 (1A15) (io), W26 I/O9 (1D15) (io), Y23 I/O64 (1A6) (io), Y24 I/O47 (1A8) (io), Y25 I/O28 (1A14) (io)
part B pins: A8 I/O162 (6A1) (io), A9 I/O156 (6B1) (io), A11 I/O142 (6B6) (io), A12 I/O134 (6B10) (io), A13 I/O128 (6B14) (io), A15 I/O114 (7B14) (io), A17 I/O101 (7B7) (io), A19 I/O87 (7B1) (io), A20 I/O80 (7A0) (io), A21 I/O73 (7A5) (io), A23 I/O51 (7A10) (io), AA2 I/O241 (4A9) (io), AA3 I/O221 (4A7) (io), AA4 I/O200 (4A4) (io), AB2 I/O242 (4A8) (io), AB3 I/O222 (4A5) (io), AB4 I/O201 (4A0) (io), AC1 I/O255 (4A6) (io), AC2 I/O243 (4A3) (io), AC3 I/O223 (4A2) (io), AD2 I/O244 (4A1) (io), B4 I/O188 (6A14) (io), B5 I/O183 (6A12) (io), B6 I/O176 (6A9) (io), B7 I/O169 (6A6) (io), B8 I/O163 (6A4) (io), B9 I/O157 (6A0) (io), B10 I/O150 (6B2) (io), B11 I/O143 (6B5) (io), B12 I/O135 (6B9) (io), B13 I/O129 (6B13) (io), B14 I/O122 (7B15) (io), B15 I/O115 (7B13) (io), B16 I/O107 (7B10) (io), B17 I/O102 (7B6) (io), B18 I/O95 (7B3) (io), B19 I/O88 (7B0) (io), B20 I/O81 (7A2) (io), B21 I/O74 (7A6) (io), B22 I/O68 (7A9) (io), B23 I/O52 (7A13) (io), C5 I/O184 (6A13) (io), C6 I/O177 (6A10) (io), C7 I/O170 (6A8) (io), C8 I/O164 (6A5) (io), C9 I/O158 (6A2) (io), C10 I/O151 (6B0) (io), C11 I/O144 (6B4) (io), C12 I/O136 (6B8) (io), C13 I/O130 (6B12) (io), C14 I/O123 (6B15) (io), C15 I/O116 (7B12) (io), C16 I/O108 (7B9) (io), C17 I/O103 (7B5) (io), C18 I/O96 (7B2) (io), C19 I/O89 (7A1) (io), C20 I/O82 (7A3) (io), C21 I/O75 (7A7) (io), C22 I/O69 (7A11) (io), C23 I/O53 (7A14) (io), D2 I/O224 (5A2) (io), D3 I/O205 (5A1) (io), D6 I/O178 (6A15) (io), D7 I/O171 (6A11) (io), D8 I/O165 (6A7) (io), D9 I/O159 (6A3) (io), D11 I/O145 (6B3) (io), D12 I/O137 (6B7) (io), D13 I/O131 (6B11) (io), D15 I/O117 (7B11) (io), D16 I/O109 (7B8) (io), D17 I/O104 (7B4) (io), D19 I/O90 (7A4) (io), D20 I/O83 (7A8) (io), D21 I/O76 (7A12) (io), D22 I/O70 (7A15) (io), E2 I/O225 (5A5) (io), E3 I/O206 (5A4) (io), E4 I/O189 (5A0) (io), F1 I/O245 (5A12) (io), F2 I/O226 (5A9) (io), F3 I/O207 (5A7) (io), F4 I/O190 (5A3) (io), G2 I/O227 (5A14) (io), G3 I/O208 (5A8) (io), G4 I/O191 (5A6) (io), H1 I/O246 (5D15) (io), H2 I/O228 (5A15) (io), H3 I/O209 (5A10) (io), J1 I/O247 (5D11) (io), J2 I/O229 (5D13) (io), J3 I/O210 (5A13) (io), J4 I/O192 (5A11) (io), K2 I/O230 (5D10) (io), K3 I/O211 (5D14) (io), L1 I/O248 (5D6) (io), L2 I/O231 (5D8) (io), L3 I/O212 (5D9) (io), L4 I/O193 (5D12) (io), M1 I/O249 (5D3) (io), M2 I/O232 (5D4) (io), M3 I/O213 (5D5) (io), M4 I/O194 (5D7) (io), N2 I/O233 (5D0) (io), N3 I/O214 (5D1) (io), N4 I/O195 (5D2) (io), P2 I/O234 (4D0) (io), R1 I/O250 (4D1) (io), R2 I/O235 (4D2) (io), R3 I/O215 (4D4) (io), R4 I/O196 (4D3) (io), T1 I/O251 (4D5) (io), T2 I/O236 (4D6) (io), T3 I/O216 (4D7) (io), T4 I/O197 (4D8) (io), U1 I/O252 (4D9) (io), U2 I/O237 (4D10) (io), U3 I/O217 (4D11) (io), U4 I/O198 (4D12) (io), V2 I/O238 (4D13) (io), V3 I/O218 (4D14) (io), W1 I/O253 (4D15) (io), W2 I/O239 (4A15) (io), W3 I/O219 (4A14) (io), W4 I/O199 (4A11) (io), Y1 I/O254 (4A13) (io), Y2 I/O240 (4A12) (io), Y3 I/O220 (4A10) (io)
part C pins: A1 NC, A2 NC, A3 GND (power), A4 NC, A5 GND (power), A6 NC, A7 GND (power), A10 GND (power), A14 GND (power), A16 NC, A18 GND (power), A22 GND (power), A24 NC, A25 GND (power), A26 NC, AA1 GND (power), AB1 NC, AB26 NC, AC4 VCC (power), AC9 VCC (power), AC13 VCC (power), AC17 VCC (power), AC22 VCC (power), AC23 TCK (in), AC26 GND (power), AD1 GND (power), AD3 TMS (in), AD23 NC, AD24 NC, AD25 NC, AD26 NC, AE1 NC, AE2 GND (power), AE3 NC, AE24 GND (power), AE25 NC, AE26 NC, AF1 NC, AF2 GND (power), AF3 NC, AF5 GND (power), AF8 NC, AF9 GND (power), AF13 GND (power), AF17 GND (power), AF20 GND (power), AF21 NC, AF22 GND (power), AF23 NC, AF24 GND (power), AF25 NC, AF26 NC, B1 NC, B2 NC, B3 GND (power), B24 NC, B25 GND (power), B26 NC, C1 NC, C2 NC, C3 NC, C4 NC, C24 TDI (in), C26 GND (power), D1 GND (power), D4 TDO (out), D5 VCC (power), D10 VCC (power), D14 VCC (power), D18 VCC (power), D23 VCC (power), E1 NC, E26 NC, F26 GND (power), G1 GND (power), G23 VCC (power), H4 VCC (power), J23 VCC (power), J26 GND (power), K1 GND (power), K4 VCC (power), N1 I3/CLK3 (in), N23 VCC (power), N24 I0/CLK0 (in), N26 GND (power), P1 GND (power), P3 I2/CLK2 (io), P4 VCC (power), P26 I1/CLK1 (in), U23 VCC (power), U26 GND (power), V1 GND (power), V4 VCC (power), W23 VCC (power), Y4 VCC (power), Y26 GND (power)

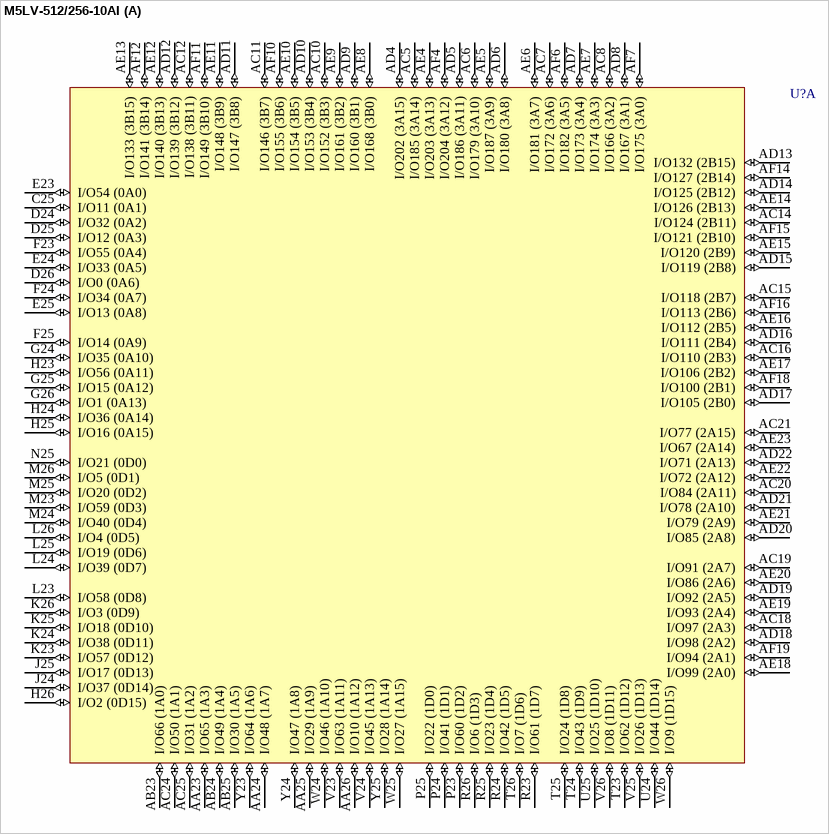
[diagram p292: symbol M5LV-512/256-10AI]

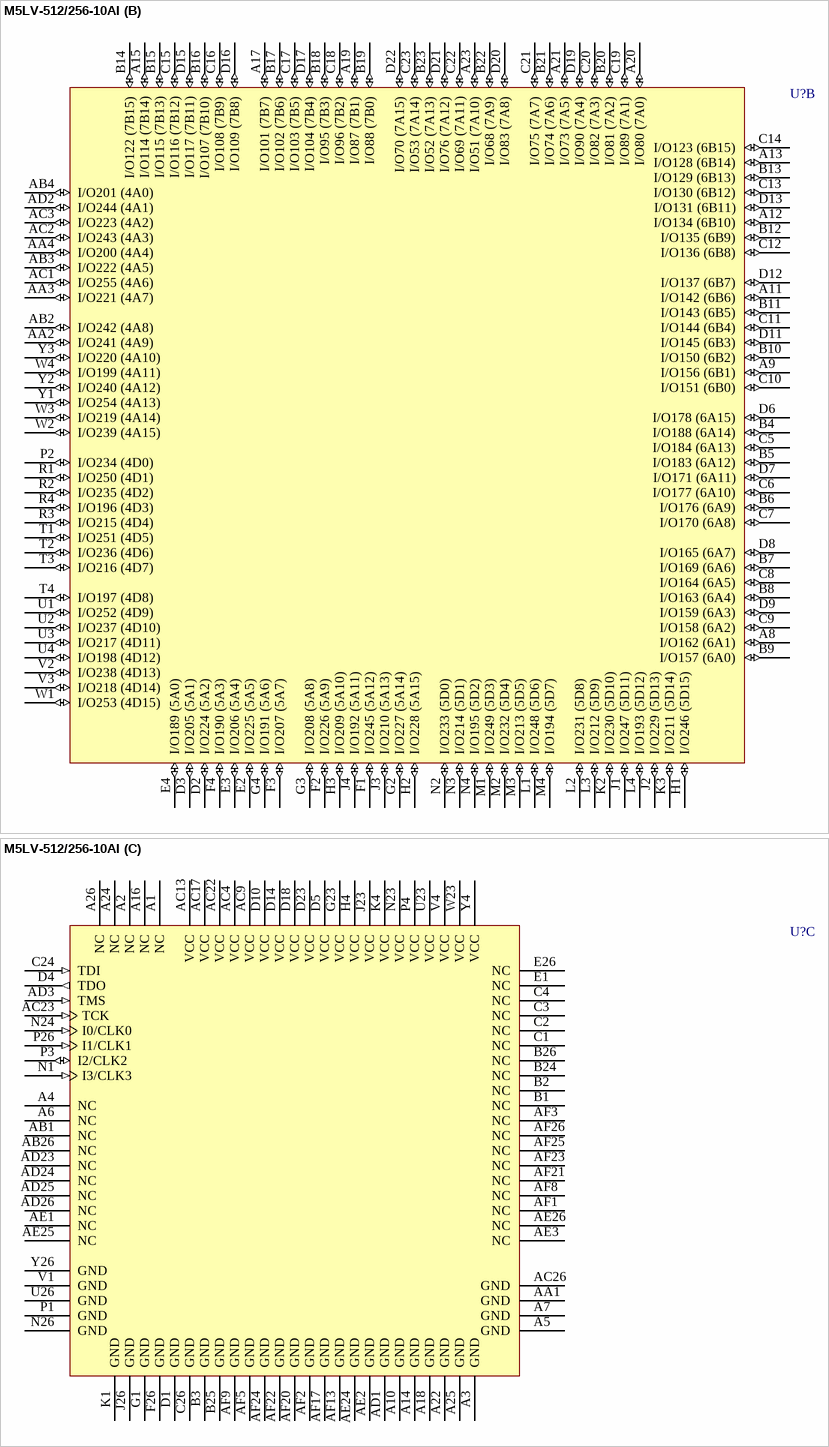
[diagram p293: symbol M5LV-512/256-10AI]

## M5LV-512/256-10AI
designator U?
High-Density and High-I/O Complex PLD
footprint SBGA352 (BGA, 352-Leads, Body 35x35mm, Pitch 1.27mm)
3D model M5LV-SBGA352 (352-Ball Super Ball Grid Array (SBGA352))
part A pins: AA23 I/O65 (1A3) (io), AA24 I/O48 (1A7) (io), AA25 I/O29 (1A9) (io), AA26 I/O10 (1A12) (io), AB23 I/O66 (1A0) (io), AB24 I/O49 (1A4) (io), AB25 I/O30 (1A5) (io), AC5 I/O185 (3A14) (io), AC6 I/O179 (3A10) (io), AC7 I/O172 (3A6) (io), AC8 I/O166 (3A2) (io), AC10 I/O152 (3B3) (io), AC11 I/O146 (3B7) (io), AC12 I/O138 (3B11) (io), AC14 I/O124 (2B11) (io), AC15 I/O118 (2B7) (io), AC16 I/O110 (2B3) (io), AC18 I/O97 (2A3) (io), AC19 I/O91 (2A7) (io), AC20 I/O84 (2A11) (io), AC21 I/O77 (2A15) (io), AC24 I/O50 (1A1) (io), AC25 I/O31 (1A2) (io), AD4 I/O202 (3A15) (io), AD5 I/O186 (3A11) (io), AD6 I/O180 (3A8) (io), AD7 I/O173 (3A4) (io), AD8 I/O167 (3A1) (io), AD9 I/O160 (3B1) (io), AD10 I/O153 (3B4) (io), AD11 I/O147 (3B8) (io), AD12 I/O139 (3B12) (io), AD13 I/O132 (2B15) (io), AD14 I/O125 (2B12) (io), AD15 I/O119 (2B8) (io), AD16 I/O111 (2B4) (io), AD17 I/O105 (2B0) (io), AD18 I/O98 (2A2) (io), AD19 I/O92 (2A5) (io), AD20 I/O85 (2A8) (io), AD21 I/O78 (2A10) (io), AD22 I/O71 (2A13) (io), AE4 I/O203 (3A13) (io), AE5 I/O187 (3A9) (io), AE6 I/O181 (3A7) (io), AE7 I/O174 (3A3) (io), AE8 I/O168 (3B0) (io), AE9 I/O161 (3B2) (io), AE10 I/O154 (3B5) (io), AE11 I/O148 (3B9) (io), AE12 I/O140 (3B13) (io), AE13 I/O133 (3B15) (io), AE14 I/O126 (2B13) (io), AE15 I/O120 (2B9) (io), AE16 I/O112 (2B5) (io), AE17 I/O106 (2B2) (io), AE18 I/O99 (2A0) (io), AE19 I/O93 (2A4) (io), AE20 I/O86 (2A6) (io), AE21 I/O79 (2A9) (io), AE22 I/O72 (2A12) (io), AE23 I/O67 (2A14) (io), AF4 I/O204 (3A12) (io), AF6 I/O182 (3A5) (io), AF7 I/O175 (3A0) (io), AF10 I/O155 (3B6) (io), AF11 I/O149 (3B10) (io), AF12 I/O141 (3B14) (io), AF14 I/O127 (2B14) (io), AF15 I/O121 (2B10) (io), AF16 I/O113 (2B6) (io), AF18 I/O100 (2B1) (io), AF19 I/O94 (2A1) (io), C25 I/O11 (0A1) (io), D24 I/O32 (0A2) (io), D25 I/O12 (0A3) (io), D26 I/O0 (0A6) (io), E23 I/O54 (0A0) (io), E24 I/O33 (0A5) (io), E25 I/O13 (0A8) (io), F23 I/O55 (0A4) (io), F24 I/O34 (0A7) (io), F25 I/O14 (0A9) (io), G24 I/O35 (0A10) (io), G25 I/O15 (0A12) (io), G26 I/O1 (0A13) (io), H23 I/O56 (0A11) (io), H24 I/O36 (0A14) (io), H25 I/O16 (0A15) (io), H26 I/O2 (0D15) (io), J24 I/O37 (0D14) (io), J25 I/O17 (0D13) (io), K23 I/O57 (0D12) (io), K24 I/O38 (0D11) (io), K25 I/O18 (0D10) (io), K26 I/O3 (0D9) (io), L23 I/O58 (0D8) (io), L24 I/O39 (0D7) (io), L25 I/O19 (0D6) (io), L26 I/O4 (0D5) (io), M23 I/O59 (0D3) (io), M24 I/O40 (0D4) (io), M25 I/O20 (0D2) (io), M26 I/O5 (0D1) (io), N25 I/O21 (0D0) (io), P23 I/O60 (1D2) (io), P24 I/O41 (1D1) (io), P25 I/O22 (1D0) (io), R23 I/O61 (1D7) (io), R24 I/O42 (1D5) (io), R25 I/O23 (1D4) (io), R26 I/O6 (1D3) (io), T23 I/O62 (1D12) (io), T24 I/O43 (1D9) (io), T25 I/O24 (1D8) (io), T26 I/O7 (1D6) (io), U24 I/O44 (1D14) (io), U25 I/O25 (1D10) (io), V23 I/O63 (1A11) (io), V24 I/O45 (1A13) (io), V25 I/O26 (1D13) (io), V26 I/O8 (1D11) (io), W24 I/O46 (1A10) (io), W25 I/O27 (1A15) (io), W26 I/O9 (1D15) (io), Y23 I/O64 (1A6) (io), Y24 I/O47 (1A8) (io), Y25 I/O28 (1A14) (io)
part B pins: A8 I/O162 (6A1) (io), A9 I/O156 (6B1) (io), A11 I/O142 (6B6) (io), A12 I/O134 (6B10) (io), A13 I/O128 (6B14) (io), A15 I/O114 (7B14) (io), A17 I/O101 (7B7) (io), A19 I/O87 (7B1) (io), A20 I/O80 (7A0) (io), A21 I/O73 (7A5) (io), A23 I/O51 (7A10) (io), AA2 I/O241 (4A9) (io), AA3 I/O221 (4A7) (io), AA4 I/O200 (4A4) (io), AB2 I/O242 (4A8) (io), AB3 I/O222 (4A5) (io), AB4 I/O201 (4A0) (io), AC1 I/O255 (4A6) (io), AC2 I/O243 (4A3) (io), AC3 I/O223 (4A2) (io), AD2 I/O244 (4A1) (io), B4 I/O188 (6A14) (io), B5 I/O183 (6A12) (io), B6 I/O176 (6A9) (io), B7 I/O169 (6A6) (io), B8 I/O163 (6A4) (io), B9 I/O157 (6A0) (io), B10 I/O150 (6B2) (io), B11 I/O143 (6B5) (io), B12 I/O135 (6B9) (io), B13 I/O129 (6B13) (io), B14 I/O122 (7B15) (io), B15 I/O115 (7B13) (io), B16 I/O107 (7B10) (io), B17 I/O102 (7B6) (io), B18 I/O95 (7B3) (io), B19 I/O88 (7B0) (io), B20 I/O81 (7A2) (io), B21 I/O74 (7A6) (io), B22 I/O68 (7A9) (io), B23 I/O52 (7A13) (io), C5 I/O184 (6A13) (io), C6 I/O177 (6A10) (io), C7 I/O170 (6A8) (io), C8 I/O164 (6A5) (io), C9 I/O158 (6A2) (io), C10 I/O151 (6B0) (io), C11 I/O144 (6B4) (io), C12 I/O136 (6B8) (io), C13 I/O130 (6B12) (io), C14 I/O123 (6B15) (io), C15 I/O116 (7B12) (io), C16 I/O108 (7B9) (io), C17 I/O103 (7B5) (io), C18 I/O96 (7B2) (io), C19 I/O89 (7A1) (io), C20 I/O82 (7A3) (io), C21 I/O75 (7A7) (io), C22 I/O69 (7A11) (io), C23 I/O53 (7A14) (io), D2 I/O224 (5A2) (io), D3 I/O205 (5A1) (io), D6 I/O178 (6A15) (io), D7 I/O171 (6A11) (io), D8 I/O165 (6A7) (io), D9 I/O159 (6A3) (io), D11 I/O145 (6B3) (io), D12 I/O137 (6B7) (io), D13 I/O131 (6B11) (io), D15 I/O117 (7B11) (io), D16 I/O109 (7B8) (io), D17 I/O104 (7B4) (io), D19 I/O90 (7A4) (io), D20 I/O83 (7A8) (io), D21 I/O76 (7A12) (io), D22 I/O70 (7A15) (io), E2 I/O225 (5A5) (io), E3 I/O206 (5A4) (io), E4 I/O189 (5A0) (io), F1 I/O245 (5A12) (io), F2 I/O226 (5A9) (io), F3 I/O207 (5A7) (io), F4 I/O190 (5A3) (io), G2 I/O227 (5A14) (io), G3 I/O208 (5A8) (io), G4 I/O191 (5A6) (io), H1 I/O246 (5D15) (io), H2 I/O228 (5A15) (io), H3 I/O209 (5A10) (io), J1 I/O247 (5D11) (io), J2 I/O229 (5D13) (io), J3 I/O210 (5A13) (io), J4 I/O192 (5A11) (io), K2 I/O230 (5D10) (io), K3 I/O211 (5D14) (io), L1 I/O248 (5D6) (io), L2 I/O231 (5D8) (io), L3 I/O212 (5D9) (io), L4 I/O193 (5D12) (io), M1 I/O249 (5D3) (io), M2 I/O232 (5D4) (io), M3 I/O213 (5D5) (io), M4 I/O194 (5D7) (io), N2 I/O233 (5D0) (io), N3 I/O214 (5D1) (io), N4 I/O195 (5D2) (io), P2 I/O234 (4D0) (io), R1 I/O250 (4D1) (io), R2 I/O235 (4D2) (io), R3 I/O215 (4D4) (io), R4 I/O196 (4D3) (io), T1 I/O251 (4D5) (io), T2 I/O236 (4D6) (io), T3 I/O216 (4D7) (io), T4 I/O197 (4D8) (io), U1 I/O252 (4D9) (io), U2 I/O237 (4D10) (io), U3 I/O217 (4D11) (io), U4 I/O198 (4D12) (io), V2 I/O238 (4D13) (io), V3 I/O218 (4D14) (io), W1 I/O253 (4D15) (io), W2 I/O239 (4A15) (io), W3 I/O219 (4A14) (io), W4 I/O199 (4A11) (io), Y1 I/O254 (4A13) (io), Y2 I/O240 (4A12) (io), Y3 I/O220 (4A10) (io)
part C pins: A1 NC, A2 NC, A3 GND (power), A4 NC, A5 GND (power), A6 NC, A7 GND (power), A10 GND (power), A14 GND (power), A16 NC, A18 GND (power), A22 GND (power), A24 NC, A25 GND (power), A26 NC, AA1 GND (power), AB1 NC, AB26 NC, AC4 VCC (power), AC9 VCC (power), AC13 VCC (power), AC17 VCC (power), AC22 VCC (power), AC23 TCK (in), AC26 GND (power), AD1 GND (power), AD3 TMS (in), AD23 NC, AD24 NC, AD25 NC, AD26 NC, AE1 NC, AE2 GND (power), AE3 NC, AE24 GND (power), AE25 NC, AE26 NC, AF1 NC, AF2 GND (power), AF3 NC, AF5 GND (power), AF8 NC, AF9 GND (power), AF13 GND (power), AF17 GND (power), AF20 GND (power), AF21 NC, AF22 GND (power), AF23 NC, AF24 GND (power), AF25 NC, AF26 NC, B1 NC, B2 NC, B3 GND (power), B24 NC, B25 GND (power), B26 NC, C1 NC, C2 NC, C3 NC, C4 NC, C24 TDI (in), C26 GND (power), D1 GND (power), D4 TDO (out), D5 VCC (power), D10 VCC (power), D14 VCC (power), D18 VCC (power), D23 VCC (power), E1 NC, E26 NC, F26 GND (power), G1 GND (power), G23 VCC (power), H4 VCC (power), J23 VCC (power), J26 GND (power), K1 GND (power), K4 VCC (power), N1 I3/CLK3 (in), N23 VCC (power), N24 I0/CLK0 (in), N26 GND (power), P1 GND (power), P3 I2/CLK2 (io), P4 VCC (power), P26 I1/CLK1 (in), U23 VCC (power), U26 GND (power), V1 GND (power), V4 VCC (power), W23 VCC (power), Y4 VCC (power), Y26 GND (power)

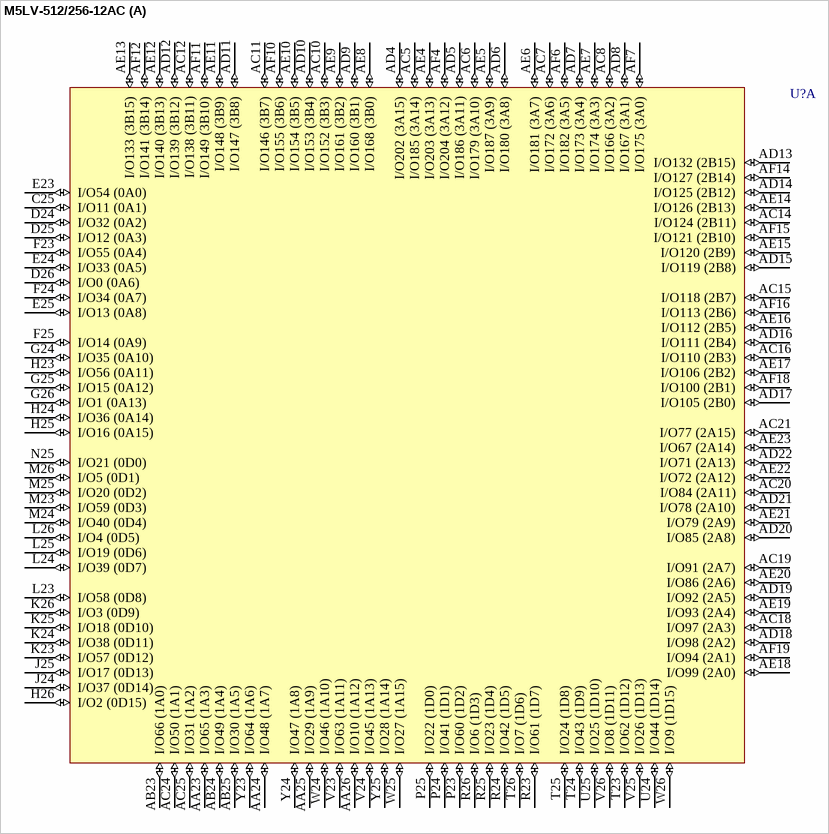
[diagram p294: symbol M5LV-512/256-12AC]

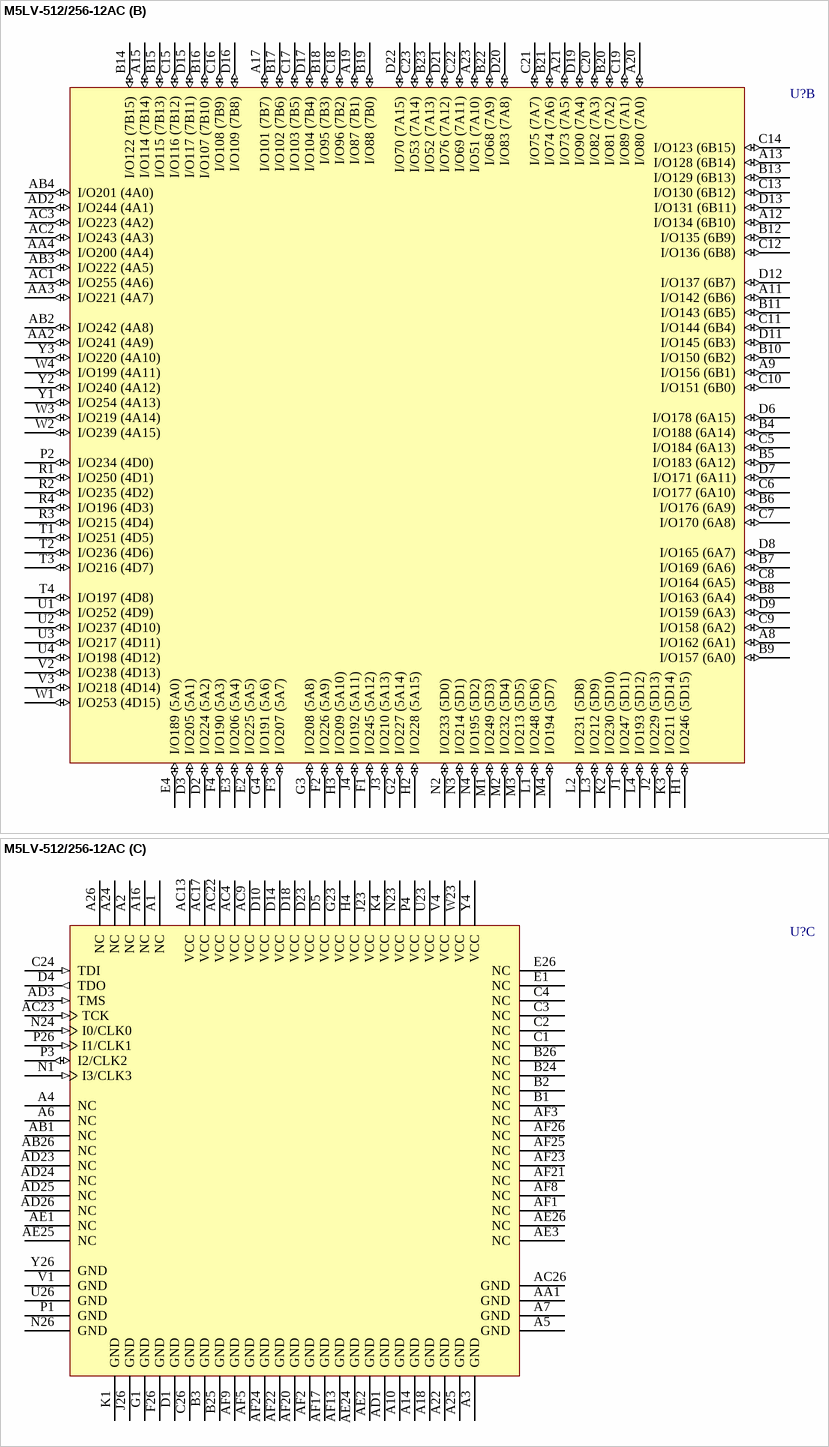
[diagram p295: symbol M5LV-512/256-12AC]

## M5LV-512/256-12AC
designator U?
High-Density and High-I/O Complex PLD
footprint SBGA352 (BGA, 352-Leads, Body 35x35mm, Pitch 1.27mm)
3D model M5LV-SBGA352 (352-Ball Super Ball Grid Array (SBGA352))
part A pins: AA23 I/O65 (1A3) (io), AA24 I/O48 (1A7) (io), AA25 I/O29 (1A9) (io), AA26 I/O10 (1A12) (io), AB23 I/O66 (1A0) (io), AB24 I/O49 (1A4) (io), AB25 I/O30 (1A5) (io), AC5 I/O185 (3A14) (io), AC6 I/O179 (3A10) (io), AC7 I/O172 (3A6) (io), AC8 I/O166 (3A2) (io), AC10 I/O152 (3B3) (io), AC11 I/O146 (3B7) (io), AC12 I/O138 (3B11) (io), AC14 I/O124 (2B11) (io), AC15 I/O118 (2B7) (io), AC16 I/O110 (2B3) (io), AC18 I/O97 (2A3) (io), AC19 I/O91 (2A7) (io), AC20 I/O84 (2A11) (io), AC21 I/O77 (2A15) (io), AC24 I/O50 (1A1) (io), AC25 I/O31 (1A2) (io), AD4 I/O202 (3A15) (io), AD5 I/O186 (3A11) (io), AD6 I/O180 (3A8) (io), AD7 I/O173 (3A4) (io), AD8 I/O167 (3A1) (io), AD9 I/O160 (3B1) (io), AD10 I/O153 (3B4) (io), AD11 I/O147 (3B8) (io), AD12 I/O139 (3B12) (io), AD13 I/O132 (2B15) (io), AD14 I/O125 (2B12) (io), AD15 I/O119 (2B8) (io), AD16 I/O111 (2B4) (io), AD17 I/O105 (2B0) (io), AD18 I/O98 (2A2) (io), AD19 I/O92 (2A5) (io), AD20 I/O85 (2A8) (io), AD21 I/O78 (2A10) (io), AD22 I/O71 (2A13) (io), AE4 I/O203 (3A13) (io), AE5 I/O187 (3A9) (io), AE6 I/O181 (3A7) (io), AE7 I/O174 (3A3) (io), AE8 I/O168 (3B0) (io), AE9 I/O161 (3B2) (io), AE10 I/O154 (3B5) (io), AE11 I/O148 (3B9) (io), AE12 I/O140 (3B13) (io), AE13 I/O133 (3B15) (io), AE14 I/O126 (2B13) (io), AE15 I/O120 (2B9) (io), AE16 I/O112 (2B5) (io), AE17 I/O106 (2B2) (io), AE18 I/O99 (2A0) (io), AE19 I/O93 (2A4) (io), AE20 I/O86 (2A6) (io), AE21 I/O79 (2A9) (io), AE22 I/O72 (2A12) (io), AE23 I/O67 (2A14) (io), AF4 I/O204 (3A12) (io), AF6 I/O182 (3A5) (io), AF7 I/O175 (3A0) (io), AF10 I/O155 (3B6) (io), AF11 I/O149 (3B10) (io), AF12 I/O141 (3B14) (io), AF14 I/O127 (2B14) (io), AF15 I/O121 (2B10) (io), AF16 I/O113 (2B6) (io), AF18 I/O100 (2B1) (io), AF19 I/O94 (2A1) (io), C25 I/O11 (0A1) (io), D24 I/O32 (0A2) (io), D25 I/O12 (0A3) (io), D26 I/O0 (0A6) (io), E23 I/O54 (0A0) (io), E24 I/O33 (0A5) (io), E25 I/O13 (0A8) (io), F23 I/O55 (0A4) (io), F24 I/O34 (0A7) (io), F25 I/O14 (0A9) (io), G24 I/O35 (0A10) (io), G25 I/O15 (0A12) (io), G26 I/O1 (0A13) (io), H23 I/O56 (0A11) (io), H24 I/O36 (0A14) (io), H25 I/O16 (0A15) (io), H26 I/O2 (0D15) (io), J24 I/O37 (0D14) (io), J25 I/O17 (0D13) (io), K23 I/O57 (0D12) (io), K24 I/O38 (0D11) (io), K25 I/O18 (0D10) (io), K26 I/O3 (0D9) (io), L23 I/O58 (0D8) (io), L24 I/O39 (0D7) (io), L25 I/O19 (0D6) (io), L26 I/O4 (0D5) (io), M23 I/O59 (0D3) (io), M24 I/O40 (0D4) (io), M25 I/O20 (0D2) (io), M26 I/O5 (0D1) (io), N25 I/O21 (0D0) (io), P23 I/O60 (1D2) (io), P24 I/O41 (1D1) (io), P25 I/O22 (1D0) (io), R23 I/O61 (1D7) (io), R24 I/O42 (1D5) (io), R25 I/O23 (1D4) (io), R26 I/O6 (1D3) (io), T23 I/O62 (1D12) (io), T24 I/O43 (1D9) (io), T25 I/O24 (1D8) (io), T26 I/O7 (1D6) (io), U24 I/O44 (1D14) (io), U25 I/O25 (1D10) (io), V23 I/O63 (1A11) (io), V24 I/O45 (1A13) (io), V25 I/O26 (1D13) (io), V26 I/O8 (1D11) (io), W24 I/O46 (1A10) (io), W25 I/O27 (1A15) (io), W26 I/O9 (1D15) (io), Y23 I/O64 (1A6) (io), Y24 I/O47 (1A8) (io), Y25 I/O28 (1A14) (io)
part B pins: A8 I/O162 (6A1) (io), A9 I/O156 (6B1) (io), A11 I/O142 (6B6) (io), A12 I/O134 (6B10) (io), A13 I/O128 (6B14) (io), A15 I/O114 (7B14) (io), A17 I/O101 (7B7) (io), A19 I/O87 (7B1) (io), A20 I/O80 (7A0) (io), A21 I/O73 (7A5) (io), A23 I/O51 (7A10) (io), AA2 I/O241 (4A9) (io), AA3 I/O221 (4A7) (io), AA4 I/O200 (4A4) (io), AB2 I/O242 (4A8) (io), AB3 I/O222 (4A5) (io), AB4 I/O201 (4A0) (io), AC1 I/O255 (4A6) (io), AC2 I/O243 (4A3) (io), AC3 I/O223 (4A2) (io), AD2 I/O244 (4A1) (io), B4 I/O188 (6A14) (io), B5 I/O183 (6A12) (io), B6 I/O176 (6A9) (io), B7 I/O169 (6A6) (io), B8 I/O163 (6A4) (io), B9 I/O157 (6A0) (io), B10 I/O150 (6B2) (io), B11 I/O143 (6B5) (io), B12 I/O135 (6B9) (io), B13 I/O129 (6B13) (io), B14 I/O122 (7B15) (io), B15 I/O115 (7B13) (io), B16 I/O107 (7B10) (io), B17 I/O102 (7B6) (io), B18 I/O95 (7B3) (io), B19 I/O88 (7B0) (io), B20 I/O81 (7A2) (io), B21 I/O74 (7A6) (io), B22 I/O68 (7A9) (io), B23 I/O52 (7A13) (io), C5 I/O184 (6A13) (io), C6 I/O177 (6A10) (io), C7 I/O170 (6A8) (io), C8 I/O164 (6A5) (io), C9 I/O158 (6A2) (io), C10 I/O151 (6B0) (io), C11 I/O144 (6B4) (io), C12 I/O136 (6B8) (io), C13 I/O130 (6B12) (io), C14 I/O123 (6B15) (io), C15 I/O116 (7B12) (io), C16 I/O108 (7B9) (io), C17 I/O103 (7B5) (io), C18 I/O96 (7B2) (io), C19 I/O89 (7A1) (io), C20 I/O82 (7A3) (io), C21 I/O75 (7A7) (io), C22 I/O69 (7A11) (io), C23 I/O53 (7A14) (io), D2 I/O224 (5A2) (io), D3 I/O205 (5A1) (io), D6 I/O178 (6A15) (io), D7 I/O171 (6A11) (io), D8 I/O165 (6A7) (io), D9 I/O159 (6A3) (io), D11 I/O145 (6B3) (io), D12 I/O137 (6B7) (io), D13 I/O131 (6B11) (io), D15 I/O117 (7B11) (io), D16 I/O109 (7B8) (io), D17 I/O104 (7B4) (io), D19 I/O90 (7A4) (io), D20 I/O83 (7A8) (io), D21 I/O76 (7A12) (io), D22 I/O70 (7A15) (io), E2 I/O225 (5A5) (io), E3 I/O206 (5A4) (io), E4 I/O189 (5A0) (io), F1 I/O245 (5A12) (io), F2 I/O226 (5A9) (io), F3 I/O207 (5A7) (io), F4 I/O190 (5A3) (io), G2 I/O227 (5A14) (io), G3 I/O208 (5A8) (io), G4 I/O191 (5A6) (io), H1 I/O246 (5D15) (io), H2 I/O228 (5A15) (io), H3 I/O209 (5A10) (io), J1 I/O247 (5D11) (io), J2 I/O229 (5D13) (io), J3 I/O210 (5A13) (io), J4 I/O192 (5A11) (io), K2 I/O230 (5D10) (io), K3 I/O211 (5D14) (io), L1 I/O248 (5D6) (io), L2 I/O231 (5D8) (io), L3 I/O212 (5D9) (io), L4 I/O193 (5D12) (io), M1 I/O249 (5D3) (io), M2 I/O232 (5D4) (io), M3 I/O213 (5D5) (io), M4 I/O194 (5D7) (io), N2 I/O233 (5D0) (io), N3 I/O214 (5D1) (io), N4 I/O195 (5D2) (io), P2 I/O234 (4D0) (io), R1 I/O250 (4D1) (io), R2 I/O235 (4D2) (io), R3 I/O215 (4D4) (io), R4 I/O196 (4D3) (io), T1 I/O251 (4D5) (io), T2 I/O236 (4D6) (io), T3 I/O216 (4D7) (io), T4 I/O197 (4D8) (io), U1 I/O252 (4D9) (io), U2 I/O237 (4D10) (io), U3 I/O217 (4D11) (io), U4 I/O198 (4D12) (io), V2 I/O238 (4D13) (io), V3 I/O218 (4D14) (io), W1 I/O253 (4D15) (io), W2 I/O239 (4A15) (io), W3 I/O219 (4A14) (io), W4 I/O199 (4A11) (io), Y1 I/O254 (4A13) (io), Y2 I/O240 (4A12) (io), Y3 I/O220 (4A10) (io)
part C pins: A1 NC, A2 NC, A3 GND (power), A4 NC, A5 GND (power), A6 NC, A7 GND (power), A10 GND (power), A14 GND (power), A16 NC, A18 GND (power), A22 GND (power), A24 NC, A25 GND (power), A26 NC, AA1 GND (power), AB1 NC, AB26 NC, AC4 VCC (power), AC9 VCC (power), AC13 VCC (power), AC17 VCC (power), AC22 VCC (power), AC23 TCK (in), AC26 GND (power), AD1 GND (power), AD3 TMS (in), AD23 NC, AD24 NC, AD25 NC, AD26 NC, AE1 NC, AE2 GND (power), AE3 NC, AE24 GND (power), AE25 NC, AE26 NC, AF1 NC, AF2 GND (power), AF3 NC, AF5 GND (power), AF8 NC, AF9 GND (power), AF13 GND (power), AF17 GND (power), AF20 GND (power), AF21 NC, AF22 GND (power), AF23 NC, AF24 GND (power), AF25 NC, AF26 NC, B1 NC, B2 NC, B3 GND (power), B24 NC, B25 GND (power), B26 NC, C1 NC, C2 NC, C3 NC, C4 NC, C24 TDI (in), C26 GND (power), D1 GND (power), D4 TDO (out), D5 VCC (power), D10 VCC (power), D14 VCC (power), D18 VCC (power), D23 VCC (power), E1 NC, E26 NC, F26 GND (power), G1 GND (power), G23 VCC (power), H4 VCC (power), J23 VCC (power), J26 GND (power), K1 GND (power), K4 VCC (power), N1 I3/CLK3 (in), N23 VCC (power), N24 I0/CLK0 (in), N26 GND (power), P1 GND (power), P3 I2/CLK2 (io), P4 VCC (power), P26 I1/CLK1 (in), U23 VCC (power), U26 GND (power), V1 GND (power), V4 VCC (power), W23 VCC (power), Y4 VCC (power), Y26 GND (power)

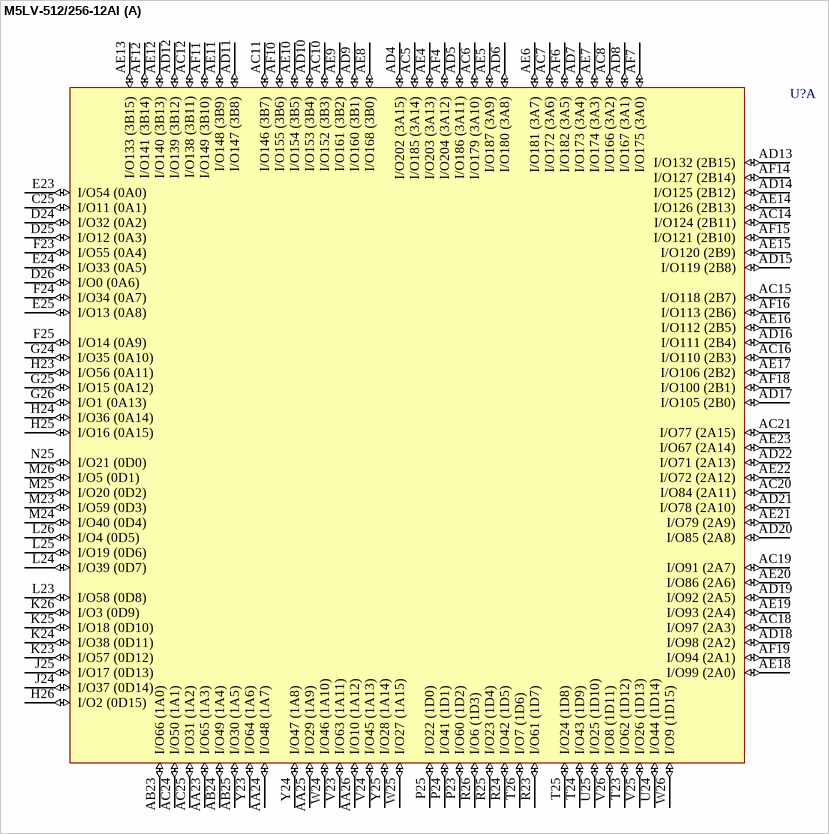
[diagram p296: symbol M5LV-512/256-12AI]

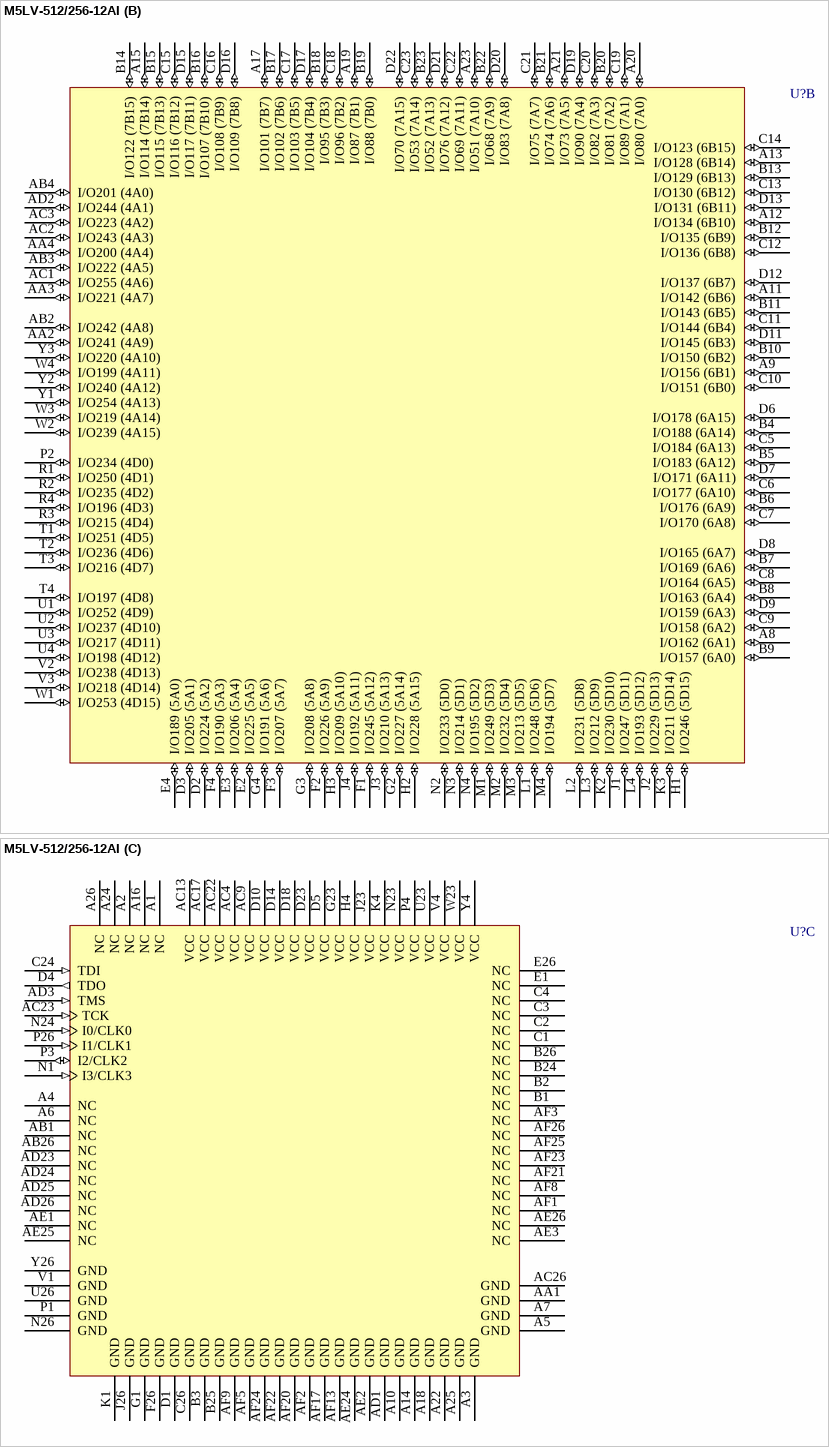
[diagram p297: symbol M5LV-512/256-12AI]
